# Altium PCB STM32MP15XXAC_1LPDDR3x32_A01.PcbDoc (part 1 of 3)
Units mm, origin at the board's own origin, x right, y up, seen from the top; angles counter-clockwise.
Board outline 89 x 120 mm, 6 copper layers (Top Layer, Signal Layer 1, Signal Layer 2, Signal Layer 3, Signal Layer 4, Bottom Layer), stack 1.556 mm thick; 93 components, 99 nets, 917 pads, 464 vias.
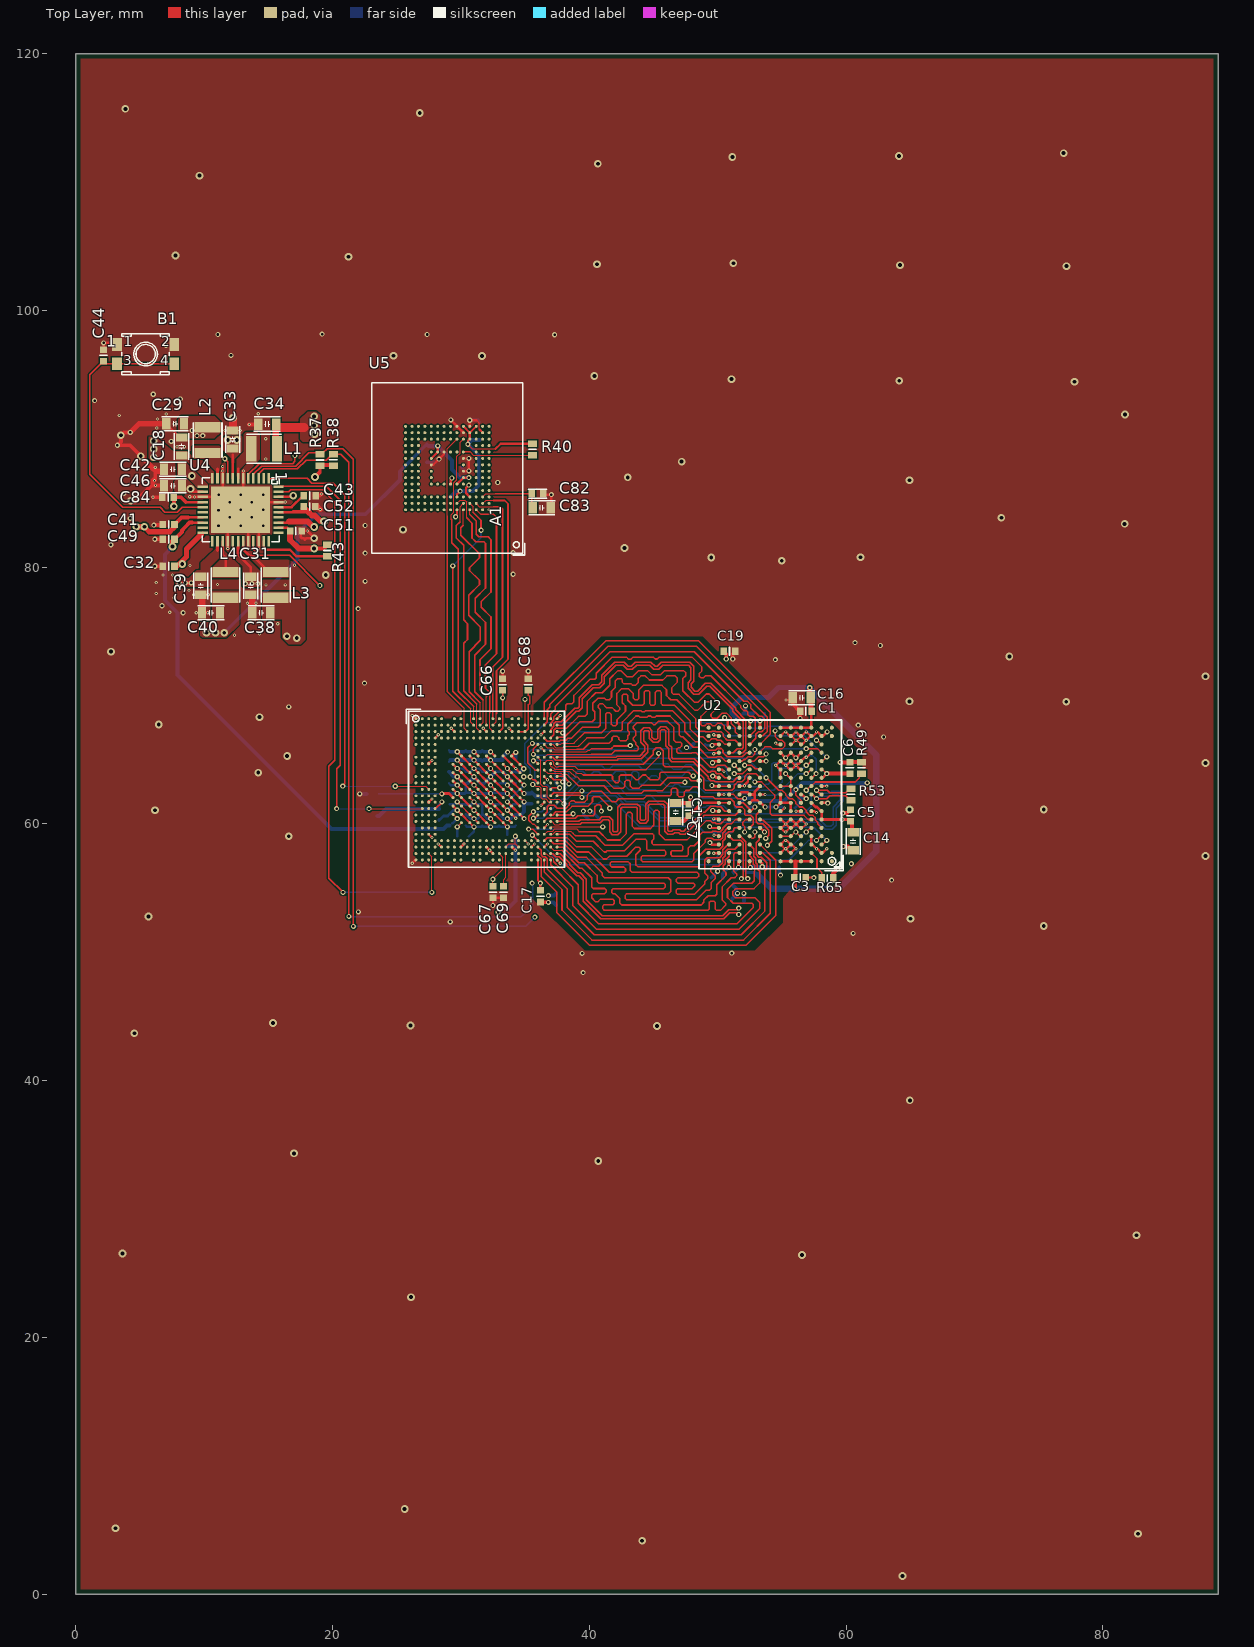
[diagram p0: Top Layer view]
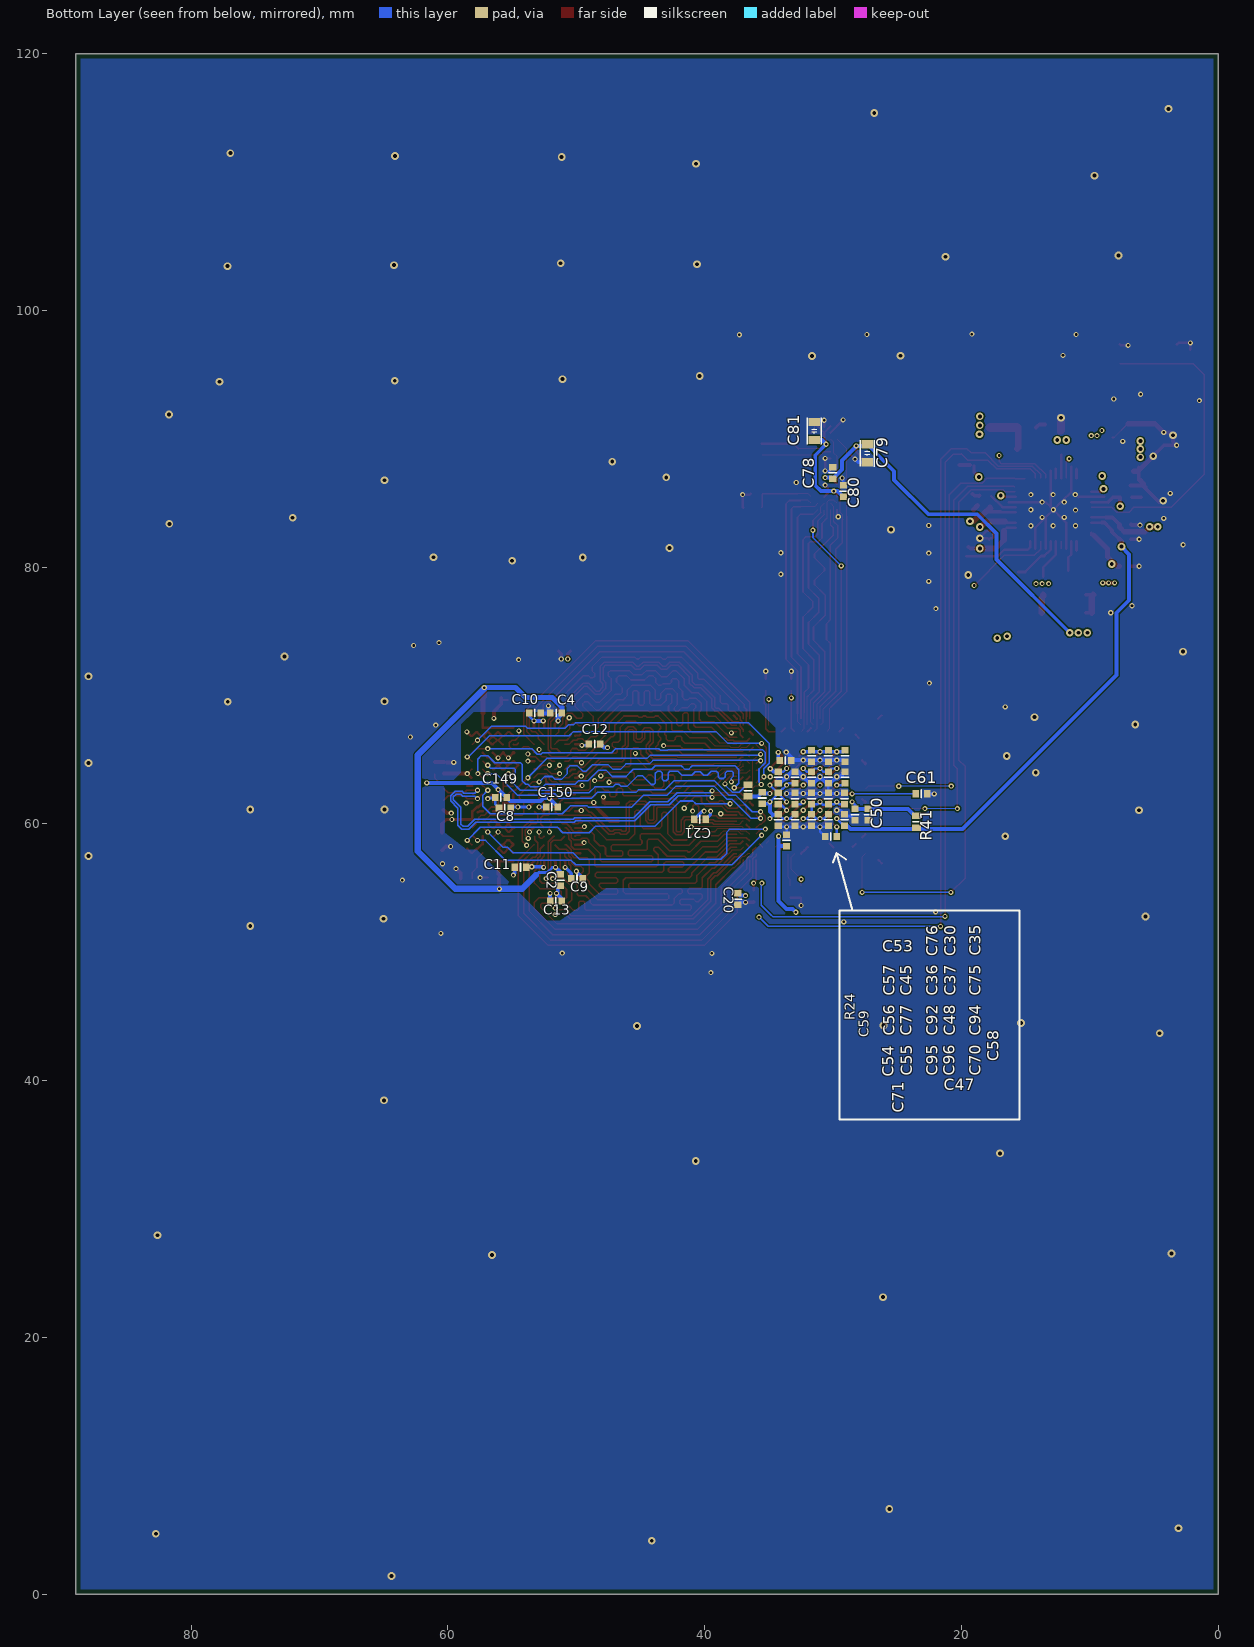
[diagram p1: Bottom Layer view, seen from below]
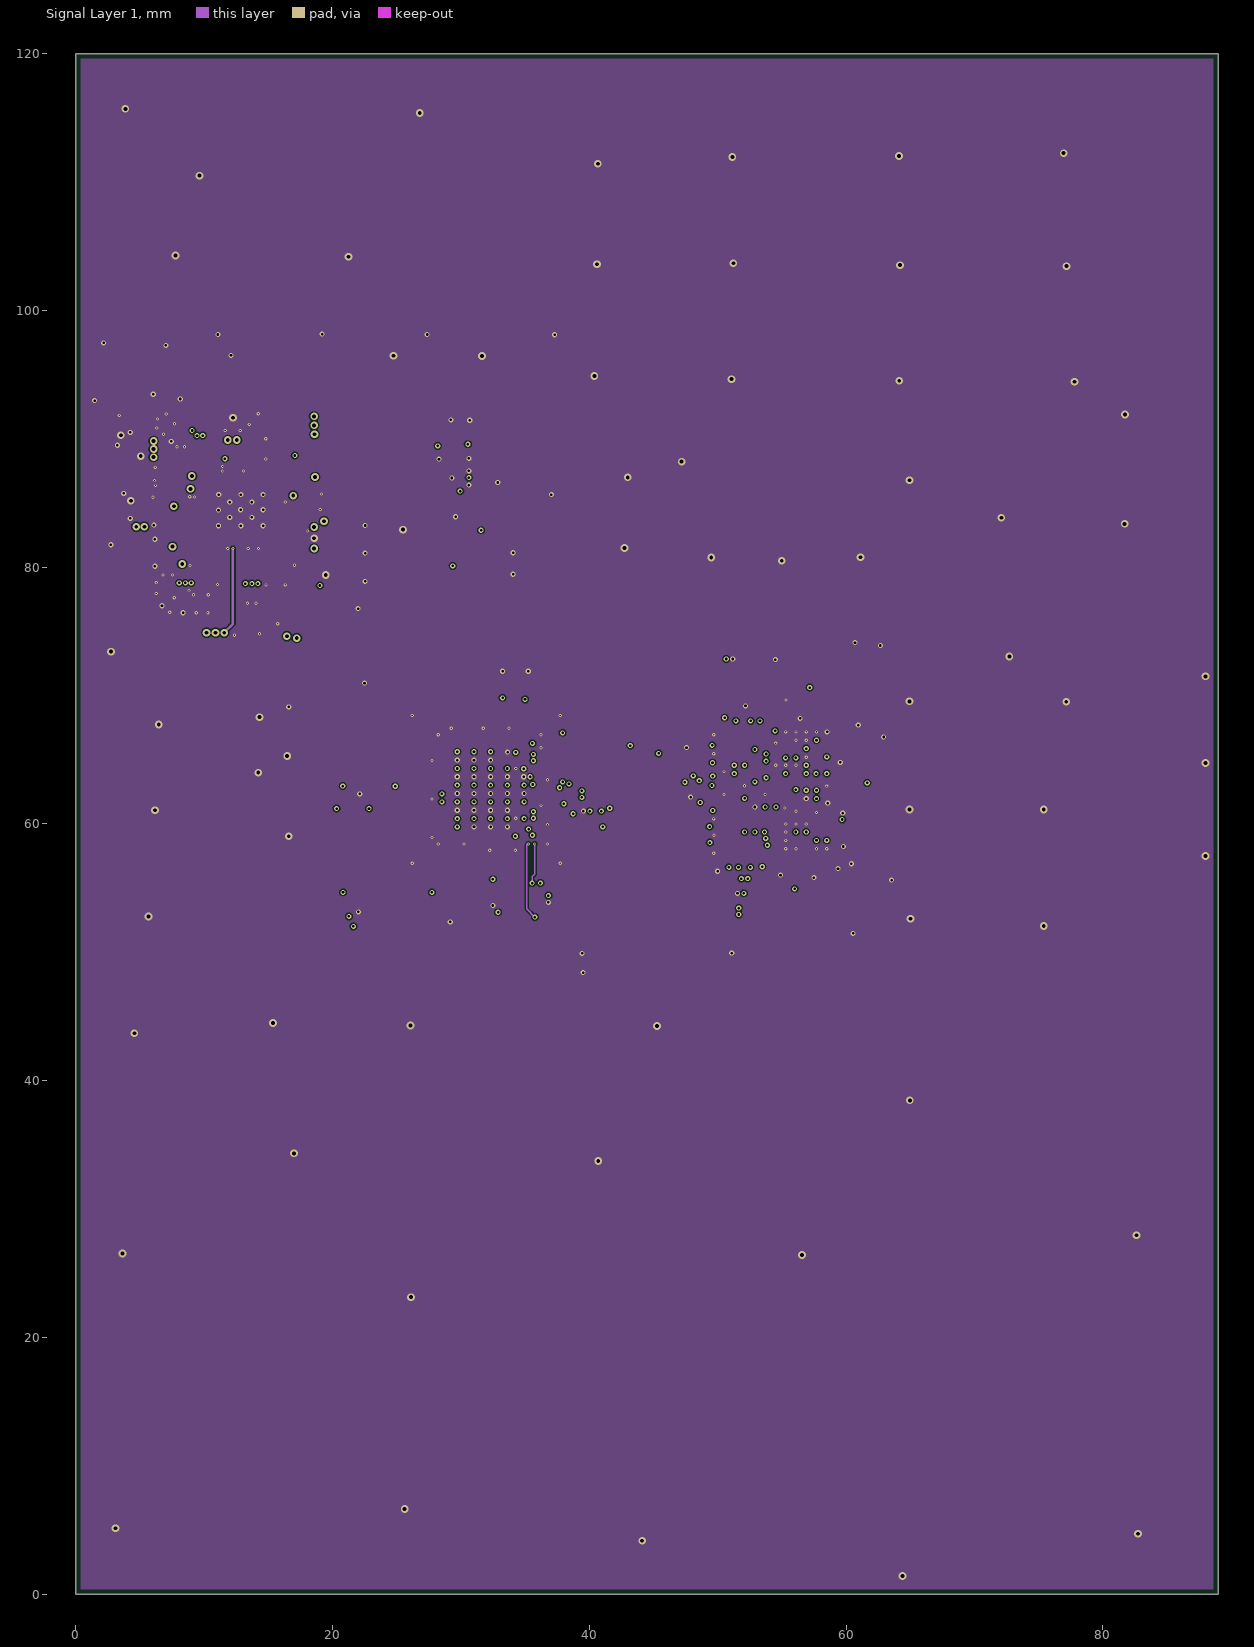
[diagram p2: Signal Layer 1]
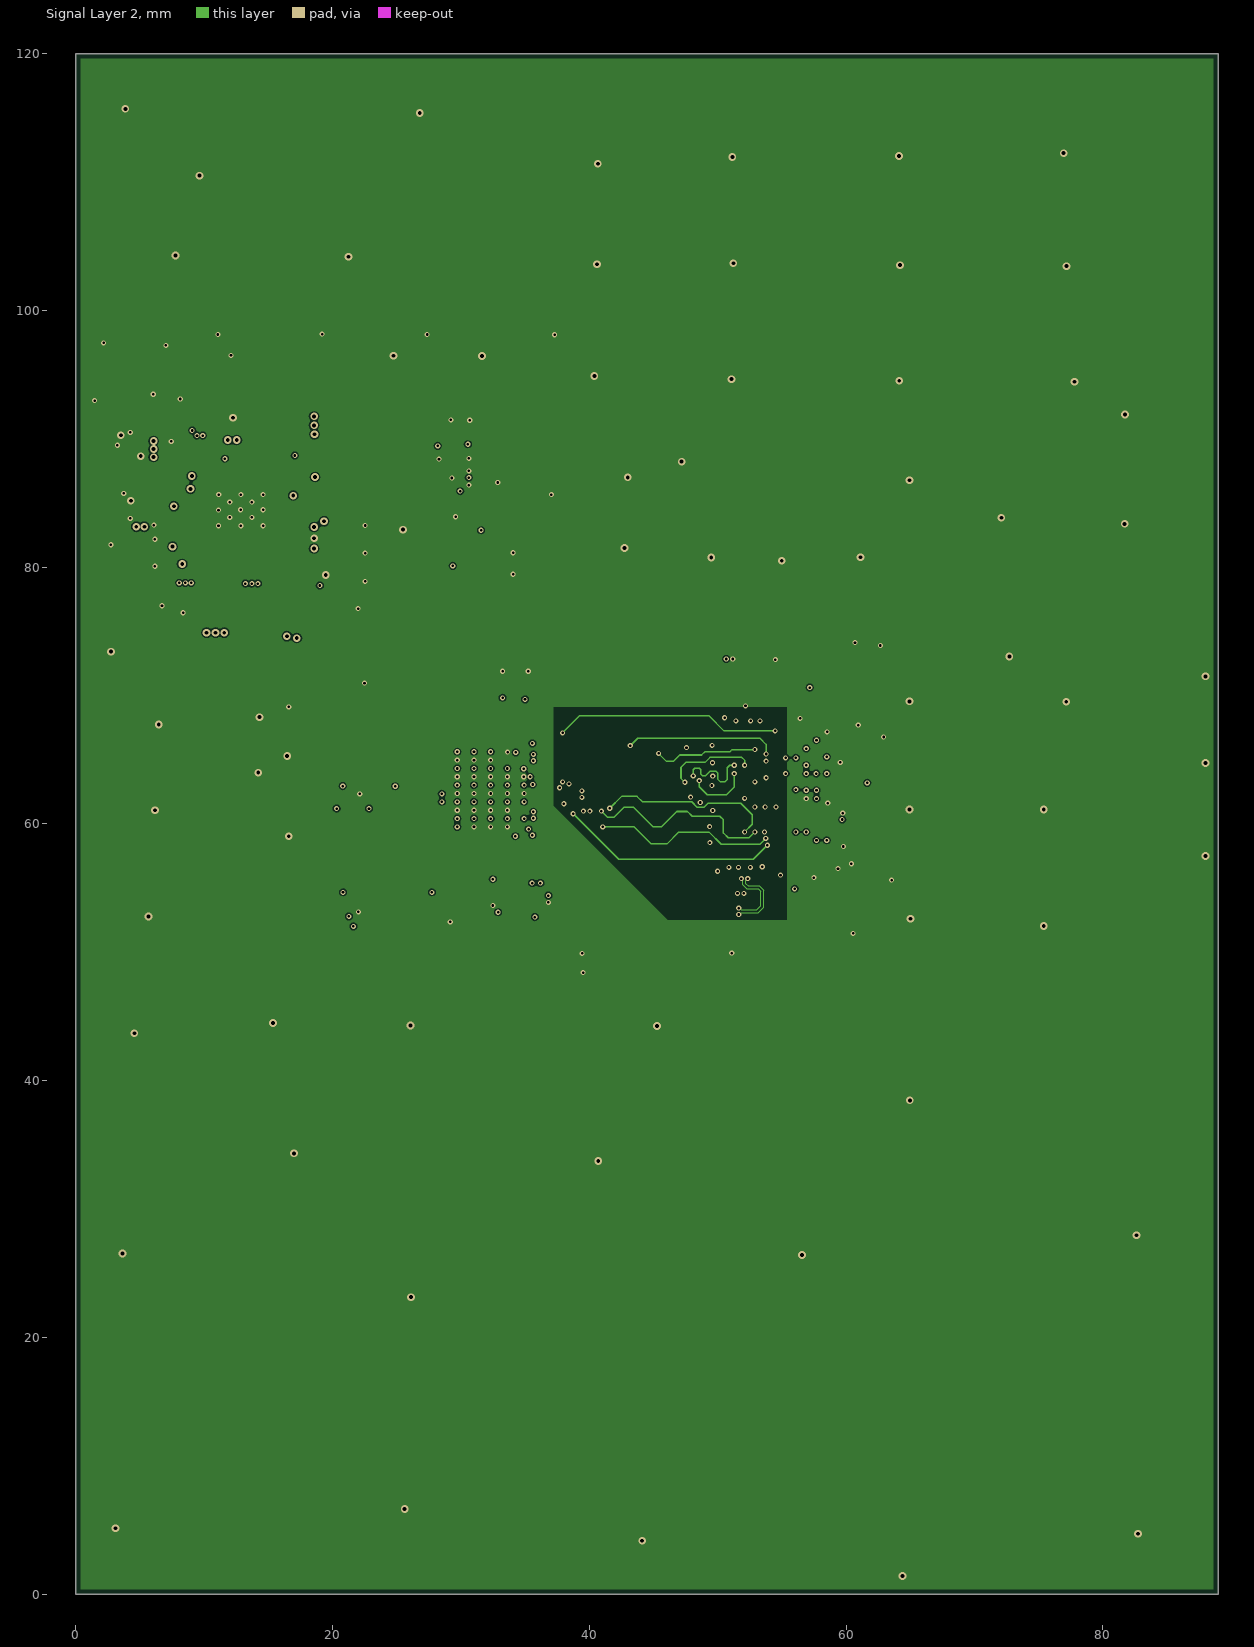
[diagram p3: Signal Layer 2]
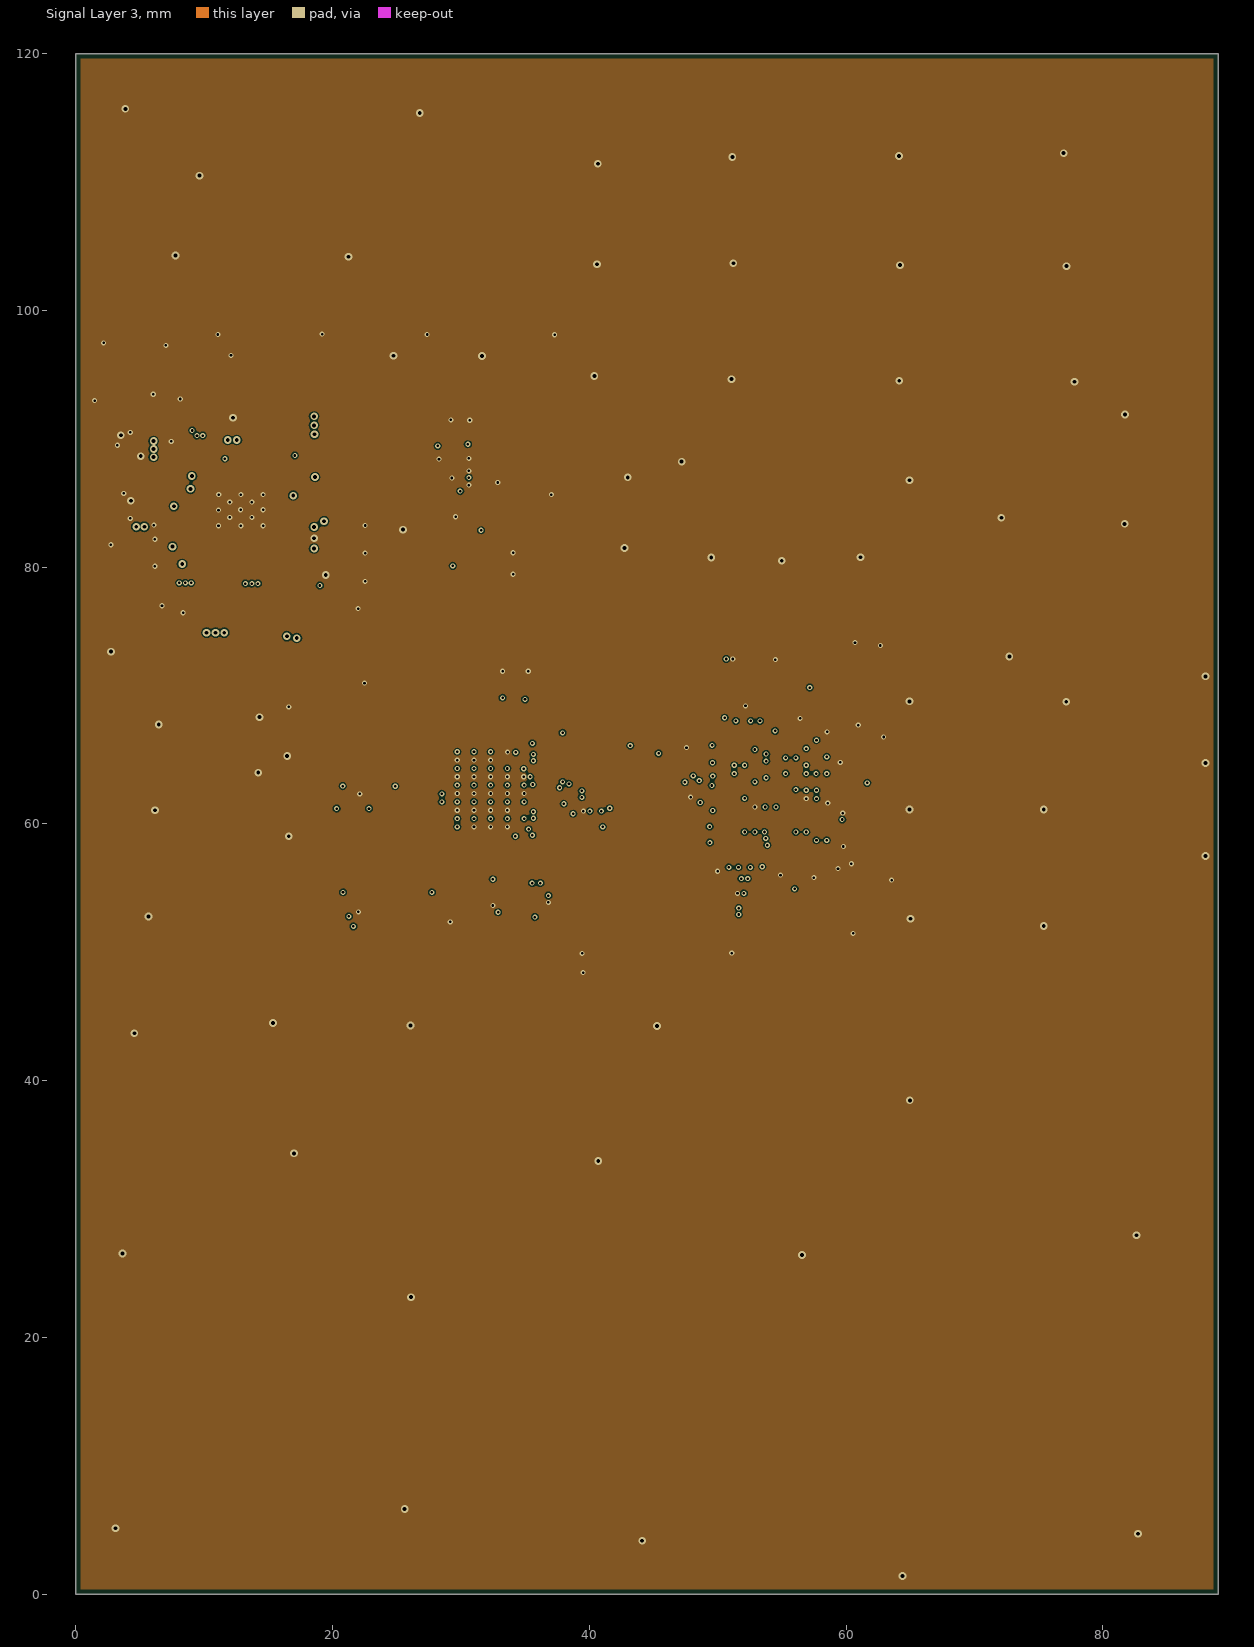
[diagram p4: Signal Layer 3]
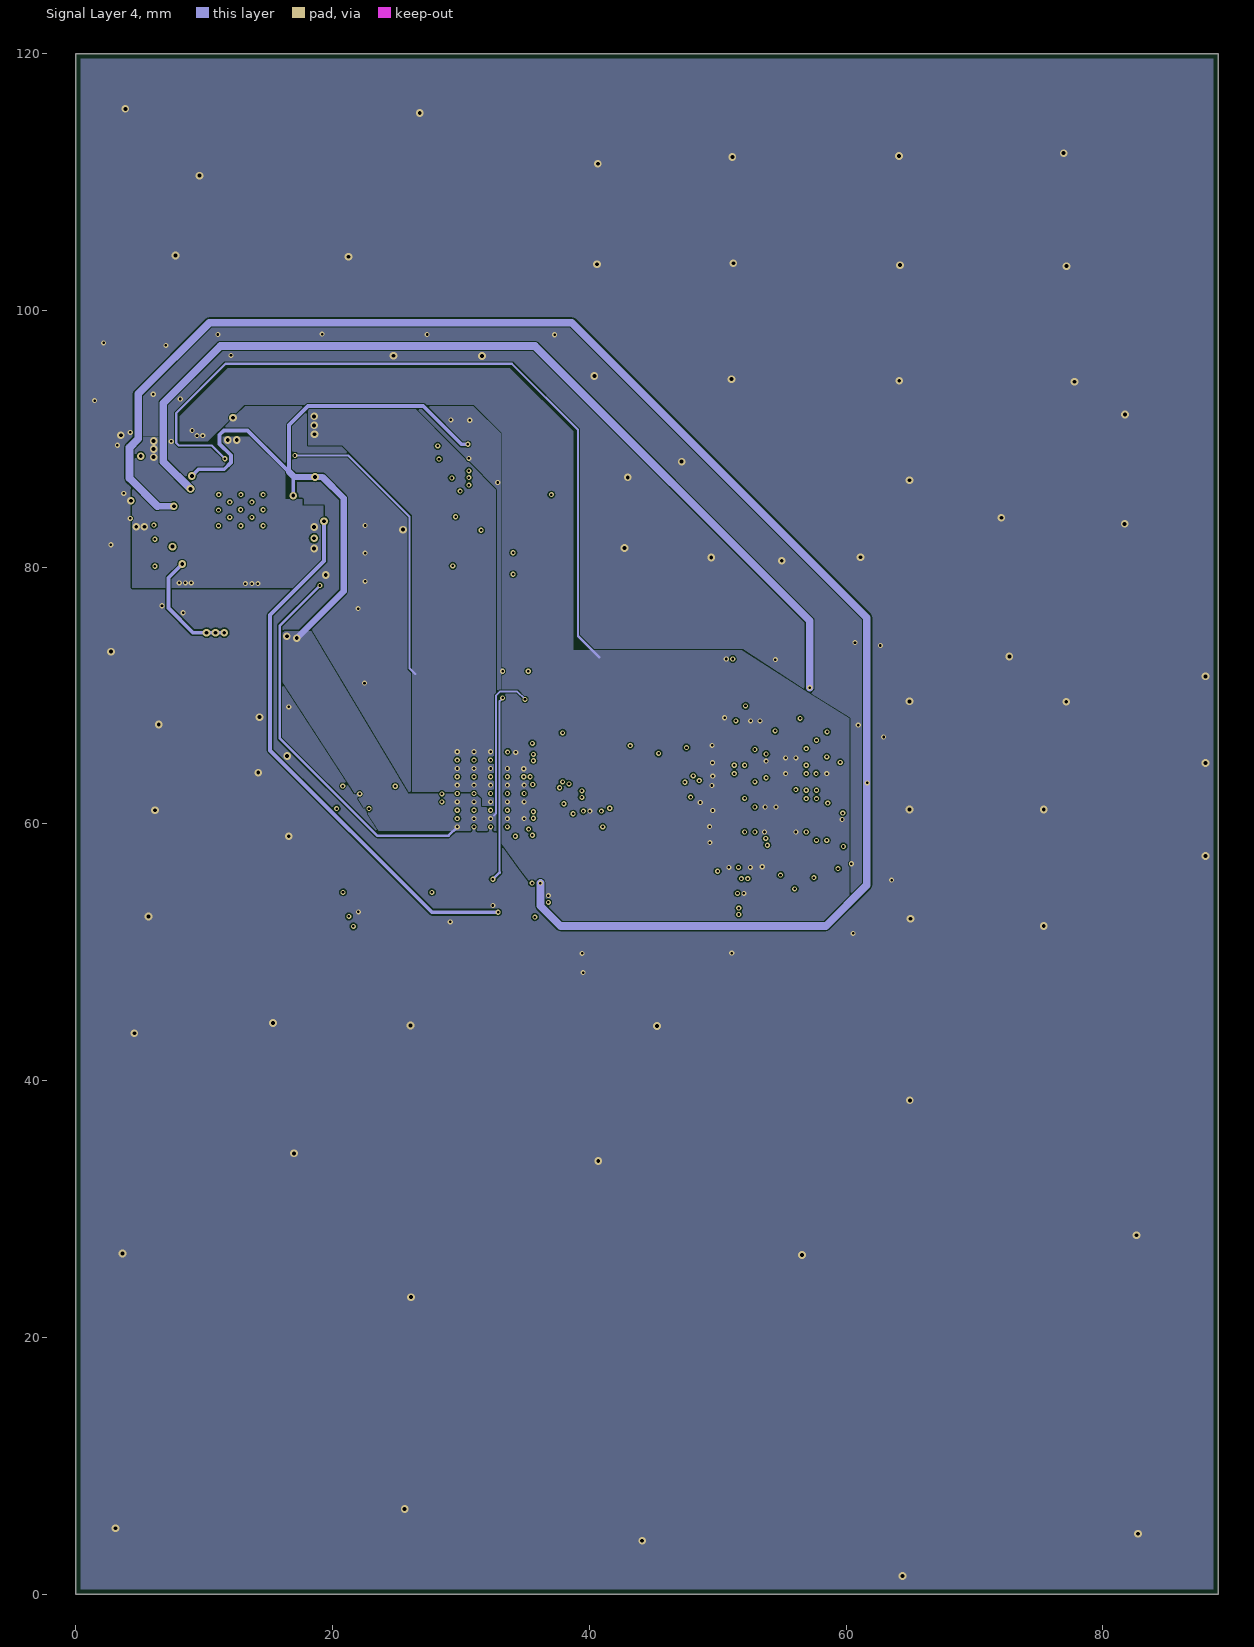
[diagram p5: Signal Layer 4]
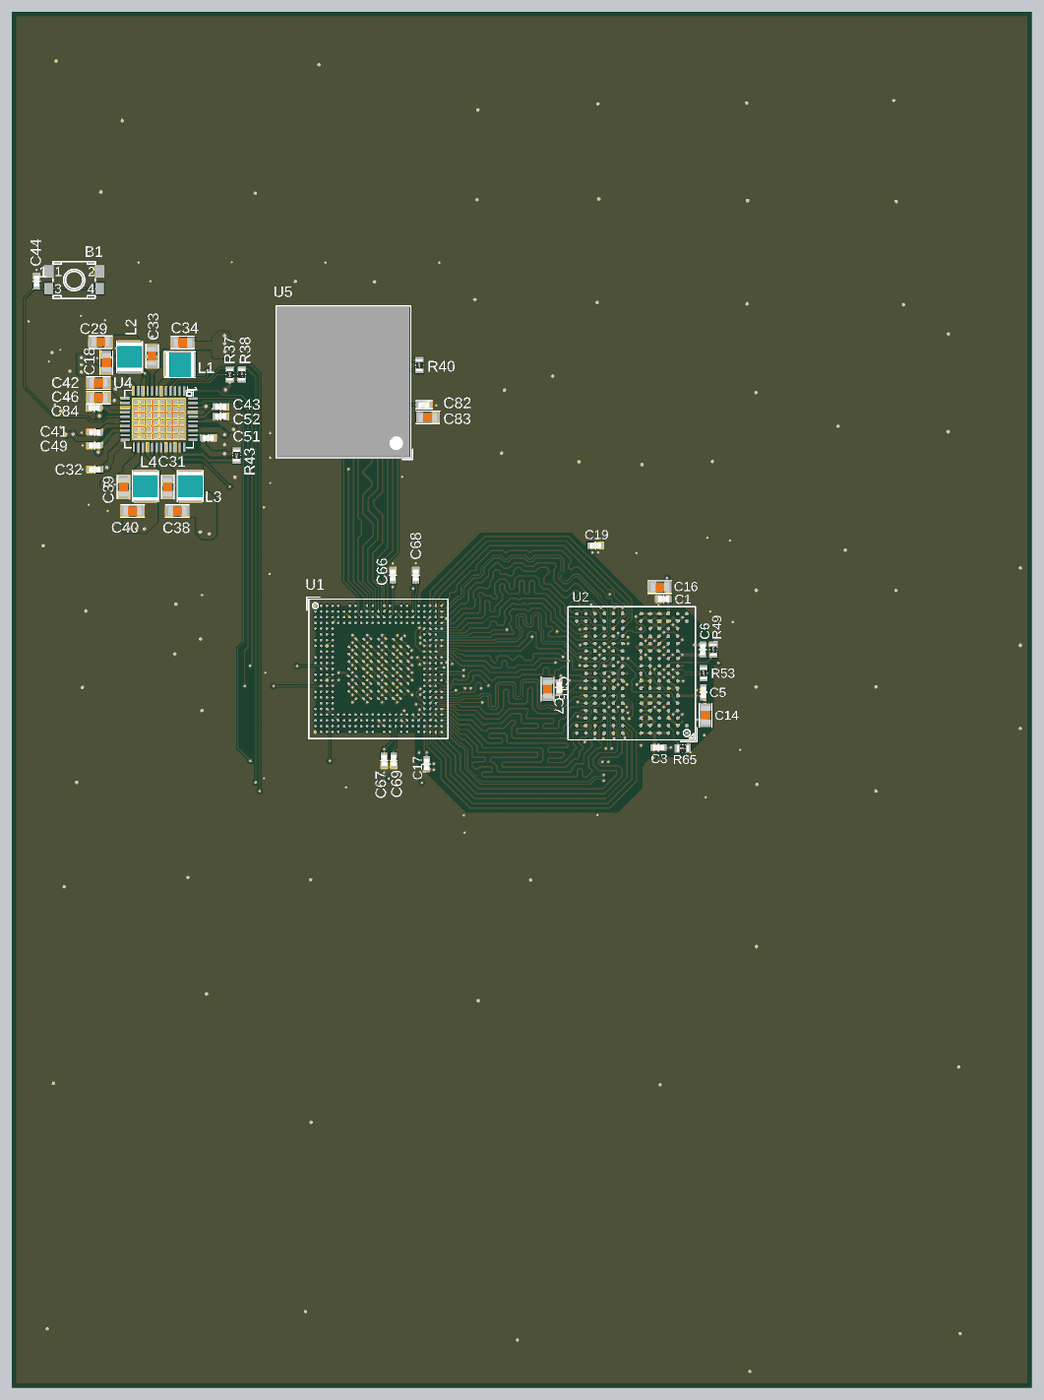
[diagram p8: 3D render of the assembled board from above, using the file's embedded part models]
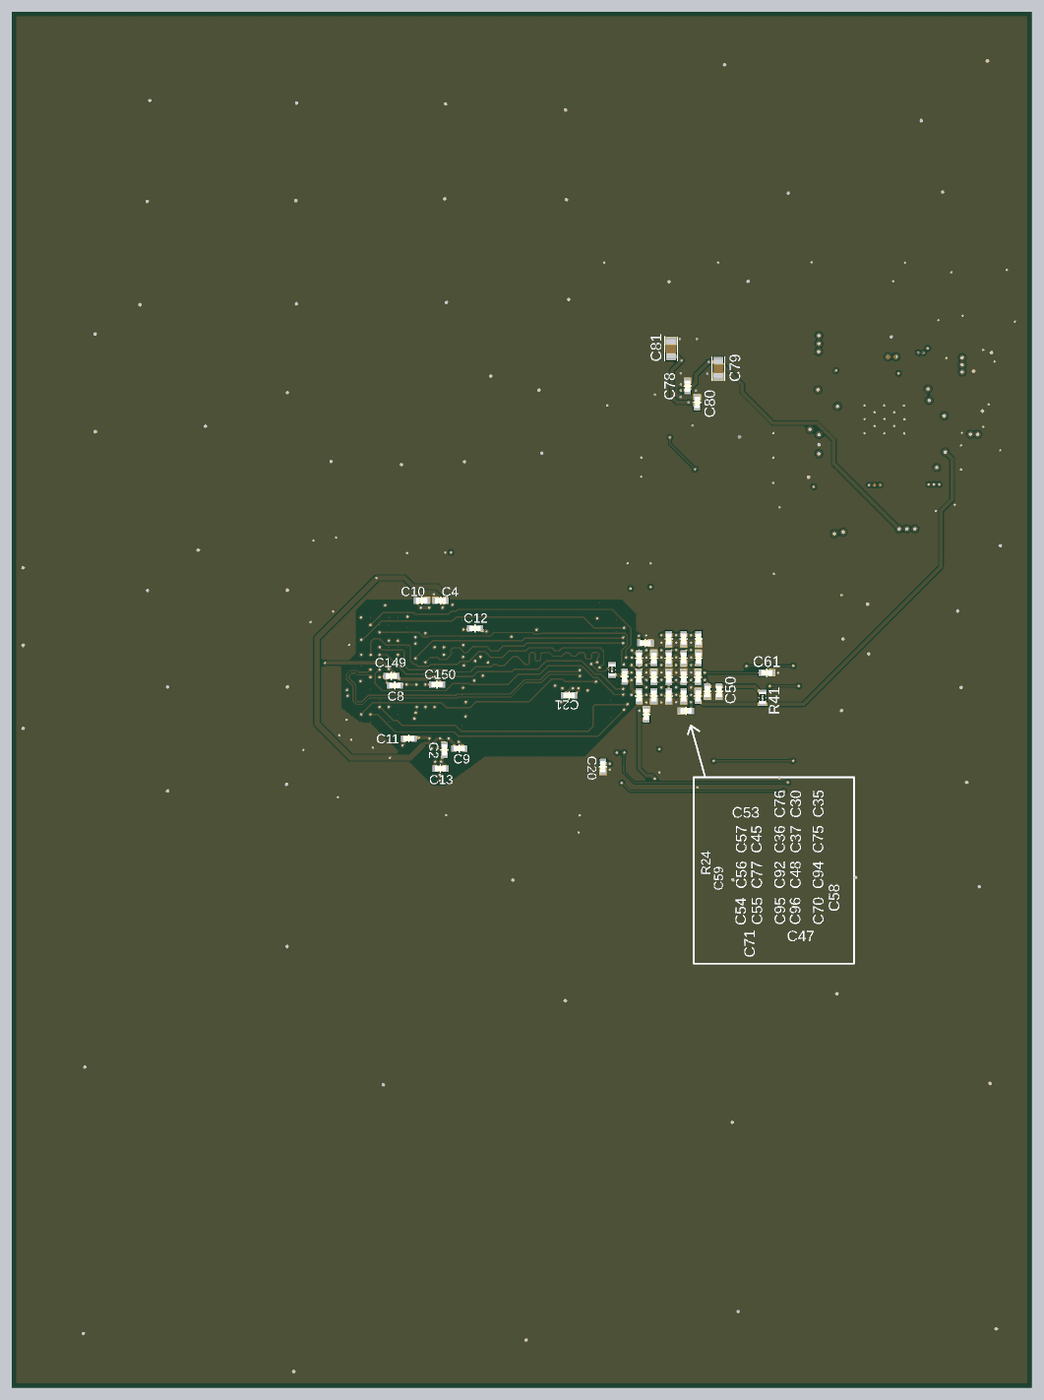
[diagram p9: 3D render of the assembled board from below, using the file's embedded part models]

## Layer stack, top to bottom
Top Solder: solder mask 0.0203, Solder Resist, Dk 3.5
Top Layer: signal copper 0.037
Dielectric 1: core 0.0986, FR-4, Dk 4.1
Signal Layer 1: signal copper 0.035
Dielectric 2: prepreg 0.13, Dk 4.25
Signal Layer 2: signal copper 0.035
Dielectric 3: core 0.885, Dk 4.25
Signal Layer 3: signal copper 0.035
Dielectric 4: prepreg 0.13, Dk 4.25
Signal Layer 4: signal copper 0.035
Dielectric 5: core 0.0986, Dk 4.1
Bottom Layer: signal copper 0.037
Bottom Solder: solder mask 0.0203, Solder Resist, Dk 3.5

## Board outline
89,120 89,0 0,0 0,120

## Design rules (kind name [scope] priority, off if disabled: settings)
BoardOutlineClearance [All] p1: gap=0.4 ignorepadtopadclearanceinfootprint=FALSE
Clearance diff [InNetClass('diff')] p1: gap=0.1 ignorepadtopadclearanceinfootprint=FALSE except(0: Arc-Hole Track-Hole SMDPad-Hole THPad-Hole Via-Hole Fill-Hole Poly-Hole Region-Hole Text-Hole; 0.08: Track-SMDPad; 0.15: Arc-Fill Track-Fill SMDPad-Fill THPad-Fill Via-Fill Fill-Fill; 0.2: Arc-THPad SMDPad-SMDPad SMDPad-THPad THPad-THPad; 0.3: Track-Track)
Clearance [InNetClass('All Nets')] p2: gap=0.1 ignorepadtopadclearanceinfootprint=FALSE except(0: Arc-Hole Track-Hole SMDPad-Hole THPad-Hole Via-Hole Fill-Hole Poly-Hole Region-Hole Text-Hole; 0.08: Track-Track Track-SMDPad; 0.15: Arc-Fill Track-Fill SMDPad-Fill THPad-Fill Via-Fill Fill-Fill)
ComponentClearance [All] p1 off: gap=0.025 collisioncheckmode=3 verticalgap=2540 showdistances=TRUE
DiffPairsRouting [All] p1: maxlimit=0.14 minlimit=0.13 mostfreqgap=0.14 toplayer_maxgap=0.13 toplayer_prefgap=0.13 toplayer_minwidth=0.09 toplayer_maxwidth=0.13 toplayer_prefwidth=0.1 midlayer1_maxgap=0.13 midlayer1_prefgap=0.13 midlayer1_minwidth=0.09 midlayer1_maxwidth=0.13 midlayer1_prefwidth=0.09 midlayer2_mingap=0.14 midlayer2_minwidth=0.09 midlayer2_maxwidth=0.09 midlayer2_prefwidth=0.09 midlayer3_mingap=0.14 midlayer3_minwidth=0.09 midlayer3_maxwidth=0.13 midlayer3_prefwidth=0.09 midlayer4_maxgap=0.13 midlayer4_prefgap=0.13 midlayer4_minwidth=0.09 midlayer4_maxwidth=0.13 midlayer4_prefwidth=0.09 bottomlayer_maxgap=0.13 bottomlayer_prefgap=0.13 bottomlayer_minwidth=0.09 bottomlayer_maxwidth=0.13 bottomlayer_prefwidth=0.1 maxuncoupledlength=0.5
FanoutControl Fanout_BGA [IsBGA] p1: bgadir=Out bgaviamode=Closest fanoutstyle=Auto fanoutdirection=Alternating viagrid=0.025 // Fanout_BGA (Default Rule)
FanoutControl Fanout_LCC [IsLCC] p2: bgadir=Out bgaviamode=Closest fanoutstyle=Auto fanoutdirection=Alternating viagrid=0.025 // Fanout_LCC (Default Rule)
FanoutControl Fanout_SOIC [IsSOIC] p3: bgadir=Out bgaviamode=Closest fanoutstyle=Auto fanoutdirection=Alternating viagrid=0.025 // Fanout_SOIC (Default Rule)
FanoutControl Fanout_Small [(CompPinCount < 5)] p4: bgadir=Out bgaviamode=Closest fanoutstyle=Auto fanoutdirection=OutThenIn viagrid=0.025 // Fanout_Small (Default Rule)
FanoutControl Fanout_Default [All] p5: bgadir=Out bgaviamode=Closest fanoutstyle=Auto fanoutdirection=Alternating viagrid=0.025 // Fanout_Default (Default Rule)
Height [All] p1 off: minheight=0 maxheight=100 prefheight=0.5
HoleSize [All] p1: absolutevalues=TRUE maxlimit=10 minlimit=0.1 maxpercent=80.000 minpercent=20.000
HoleToHoleClearance [All] p1: gap=0.25 allowstackedmicrovias=TRUE
Length Length_SDMMC1 [InNetClass('NETC_SDMMC1')] p1: maxlimit=86 minlimit=81
MatchedLengths [All] p1: tolerance=25.4 checknetsindiffpair=FALSE checkdiffpairvsdiffpair=TRUE checkxsignals=TRUE checkothers=TRUE
MinimumSolderMaskSliver [All] p1: minsoldermaskwidth=0
PlaneClearance [All] p1: clearance=0.6
PlaneConnect [All] p1: planeconnectstyle=Direct reliefexpansion=0.508 reliefentries=4 reliefconductorwidth=0.254 reliefairgap=0.254
PolygonConnect PolygonConnect_notr [All vs (IsNamedPolygon('NO TR'))] p1: connectstyle=Direct reliefconductorwidth=0.254 reliefentries=4 polygonreliefangle="90 Angle" airgapwidth=0.254
PolygonConnect PolygonConnect_VTT_DDR [All vs IsNamedPolygon('VTT_DDR_BOT')] p2: connectstyle=Direct reliefconductorwidth=0.254 reliefentries=4 polygonreliefangle="45 Angle" airgapwidth=0.254
PolygonConnect [All] p3: connectstyle=Direct reliefconductorwidth=0.254 reliefentries=4 polygonreliefangle="45 Angle" airgapwidth=0.254
RoomDefinition U_1LPDDR3_32bits [InComponentClass('U_1LPDDR3_32bits')] p1 off: confinementstyle=ConfineIn formatcopy=TRUE lockcomponents=FALSE outline 90.122,1.416 267.981,1.416 267.981,16.341 90.122,16.341
RoomDefinition U_STM32_MPU_IOs [InComponentClass('U_STM32_MPU_IOs')] p2 off: confinementstyle=ConfineIn formatcopy=TRUE lockcomponents=FALSE outline 88.575,2.075 139.375,2.075 139.375,27.475 88.575,27.475
RoomDefinition U_Power_MPU [InComponentClass('U_Power_MPU')] p3 off: confinementstyle=ConfineIn formatcopy=TRUE lockcomponents=FALSE outline 87.122,16.916 100.898,16.916 100.898,22.892 87.122,22.892
RoomDefinition U_eMMC [InComponentClass('U_eMMC')] p4 off: confinementstyle=ConfineIn formatcopy=TRUE lockcomponents=FALSE outline 87.122,1.416 129.449,1.416 129.449,15.666 87.122,15.666
RoomDefinition U_Power_PMIC [InComponentClass('U_Power_PMIC')] p5 off: confinementstyle=ConfineIn formatcopy=TRUE lockcomponents=FALSE outline 87.122,8.666 203.578,8.666 203.578,17.666 87.122,17.666
RoutingVias RoutingVias_GND [InNetClass('GND')] p1: holewidth=0.3 width=0.6 viastyle="Through Hole" minholewidth=0.1 minwidth=0.25 maxholewidth=0.3 maxwidth=0.6
RoutingVias RoutingVias_ALIMS [InNetClass('ALIMS')] p2: holewidth=0.3 width=0.6 viastyle="Through Hole" minholewidth=0.2 minwidth=0.4 maxholewidth=0.3 maxwidth=0.6
RoutingVias [All] p3: holewidth=0.2 width=0.4 viastyle="Through Hole" minholewidth=0.1 minwidth=0.25 maxholewidth=0.3 maxwidth=0.6
SilkToSilkClearance [All] p1: silktosilkclearance=0
SilkToSolderMaskClearance [IsPad] p1: minsilkscreentomaskgap=0 clearancetoexposedcopper=TRUE
SolderMaskExpansion [All] p1: expansion=0.05 istentingtop=FALSE
Width VDD2_DDR [InNet('VDD2_DDR')] p1: maxlimit=0.5 minlimit=0.1 preferedwidth=0.3
Width Width_VCORE [InNet('VDD_CORE')] p2: maxlimit=0.7 minlimit=0.1 preferedwidth=0.3 midlayer1_minwidth=0.12 midlayer2_minwidth=0.12 midlayer3_minwidth=0.12 midlayer4_minwidth=0.12 bottomlayer_minwidth=0.12 minimp=50.000000 maximp=50.000000 favimp=50.000000
Width Width_gnd [InNet('GND')] p3: maxlimit=0.7 minlimit=0.09 preferedwidth=0.3
Width [All] p4: maxlimit=0.6 minlimit=0.09 preferedwidth=0.127 toplayer_prefwidth=0.12 midlayer1_minwidth=0.1 midlayer1_prefwidth=0.12 midlayer2_prefwidth=0.12 midlayer3_minwidth=0.127 midlayer4_minwidth=0.1 midlayer4_prefwidth=0.12 bottomlayer_prefwidth=0.12 minimp=50.000000 maximp=50.000000 favimp=50.000000
15 further rules are at their usual default settings.

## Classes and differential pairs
component class U_1LPDDR3_32bits: C1 C2 C3 C4 C5 C6 C7 C8 C9 C10 C11 C12 C13 C14 C15 C16 C19 C20 C21 C149 C150 R49 R53 R65 U2
differential pair class DIFF_CLK: DDR_CLK
differential pair class DIFF_DQS1: DDR_DQS1
differential pair class DIFF_DQS0: DDR_DQS0
polygon class POLY_DIRECT_ALL: NETC906_2_L01_P192
component class U_Power_MPU: C30 C35 C36 C37 C45 C47 C48 C50 C53 C54 C55 C56 C57 C58 C59 C61 C66 C67 C68 C69 C70 C71 C75 C76 C77 C92 C94 C95 C96 R41
component class U_Power_PMIC: B1 C18 C29 C31 C32 C33 C34 C38 C39 C40 C41 C42 C43 C44 C46 C49 C51 C52 C84 L1 L2 L3 L4 R43 U4
component class U_eMMC: C78 C79 C80 C81 C82 C83 R40 U5
component class U_STM32_MPU_IOs: C17 R24 R37 R38 U1
net class eMMC_SDIO2_D[0..7]: eMMC_SDIO2_D0 eMMC_SDIO2_D1 eMMC_SDIO2_D2 eMMC_SDIO2_D3 eMMC_SDIO2_D4 eMMC_SDIO2_D5 eMMC_SDIO2_D6 eMMC_SDIO2_D7
differential pair DDR_CLK: +DDR_CLK_P -DDR_CLK_N
differential pair DDR_DQS0: +DDR_DQS0_P -DDR_DQS0_N
differential pair DDR_DQS1: +DDR_DQS1_P -DDR_DQS1_N
differential pair DDR_DQS2: +DDR_DQS2_P -DDR_DQS2_N
differential pair DDR_DQS3: +DDR_DQS3_P -DDR_DQS3_N

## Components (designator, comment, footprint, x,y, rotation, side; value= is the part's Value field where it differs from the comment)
B1 "SW-PUSH-TS-02H-Blue" SWI_JIUBABA_C-TS-02H-2-5-B-V-T_R_BLUE 5.45,96.6 r0 top
C1 "Capacitor" C0402 56.875,68.775 r180 top
C2 "Capacitor" C0402 51.25,55.625 r270 bottom
C3 "Capacitor" C0402 56.425,55.825 r0 top
C4 "Capacitor" C0402 51.575,68.65 r0 bottom
C5 "Capacitor" C0402 60.35,60.65 r90 top
C6 "Capacitor" C0402 60.3,64.375 r90 top
C7 "Capacitor" C0402 47.775,61.075 r90 top
C8 "Capacitor" C0402 55.575,61.25 r0 bottom
C9 "Capacitor" C0402 49.95,55.75 r180 bottom
C10 "Capacitor" C0402 53.225,68.65 r180 bottom
C11 "Capacitor" C0402 54.35,56.625 r0 bottom
C12 "Capacitor" C0402 48.575,66.225 r180 bottom
C13 "Capacitor" C0402 51.6,54 r180 bottom
C14 "Capacitor" C0603 60.55,58.65 r90 top
C15 "Capacitor" C0603 46.75,60.925 r270 top
C16 "Capacitor" C0603 56.55,69.825 r0 top
C17 "Capacitor" C0402 36.2,54.375 r270 top
C18 "Capacitor" C0603 8.25,89.4 r270 top
C19 "Capacitor" C0402 50.925,73.45 r0 top
C20 "Capacitor" C0402 37.425,54.15 r270 bottom
C21 "Capacitor" C0402 40.375,60.375 r180 bottom
C29 "Capacitor" C0603 7.75,91.175 r0 top
C30 "Capacitor" C0402 30.375,65.3 r90 bottom
C31 "Capacitor" C0603 13.625,78.55 r90 top
C32 "Capacitor" C0402 7.25,80.075 r0 top
C33 "Capacitor" C0603 12.25,89.95 r270 top
C34 "Capacitor" C0603 14.925,91.15 r0 top
C35 "Capacitor" C0402 29.075,65.3 r90 bottom
C36 "Capacitor" C0402 31.675,63.625 r90 bottom
C37 "Capacitor" C0402 30.375,63.625 r90 bottom
C38 "Capacitor" C0603 14.45,76.45 r0 top
C39 "Capacitor" C0603 9.75,78.55 r90 top
C40 "Capacitor" C0603 10.55,76.45 r0 top
C41 "Capacitor" C0402 7.25,83.325 r0 top
C42 "Capacitor" C0603 7.575,87.625 r0 top
C43 "Capacitor" C0402 18.234,85.562 r0 top
C44 "Capacitor" C0402 2.175,96.5 r270 top
C45 "Capacitor" C0402 32.975,63.625 r270 bottom
C46 "Capacitor" C0603 7.575,86.35 r0 top
C47 "Capacitor" C0402 30.175,59.025 r180 bottom
C48 "Capacitor" C0402 30.375,61.975 r270 bottom
C49 "Capacitor" C0402 7.25,82.175 r0 top
C50 "Capacitor" C0402 27.275,60.725 r90 bottom
C51 "Capacitor" C0402 17.15,82.825 r180 top
C52 "Capacitor" C0402 18.225,84.725 r180 top
C53 "Capacitor" C0402 33.725,64.95 r0 bottom
C54 "Capacitor" C0402 34.275,60.325 r90 bottom
C55 "Capacitor" C0402 32.975,60.325 r90 bottom
C56 "Capacitor" C0402 34.275,61.975 r90 bottom
C57 "Capacitor" C0402 34.275,63.625 r90 bottom
C58 "Capacitor" C0402 28.3,60.725 r90 bottom
C59 "Capacitor" C0402 35.525,62.025 r270 bottom
C61 "Capacitor" C0402 23.125,62.35 r0 bottom
C66 "Capacitor" C0402 33.25,70.85 r270 top
C67 "Capacitor" C0402 32.5,54.7 r90 top
C68 "Capacitor" C0402 35.25,70.85 r270 top
C69 "Capacitor" C0402 33.325,54.7 r90 top
C70 "Capacitor" C0402 29.125,60.325 r270 bottom
C71 "Capacitor" C0402 33.625,58.725 r270 bottom
C75 "Capacitor" C0402 29.075,63.625 r270 bottom
C76 "Capacitor" C0402 31.675,65.3 r90 bottom
C77 "Capacitor" C0402 32.975,61.975 r270 bottom
C78 "Capacitor" C0402 30.025,87.35 r270 bottom
C79 "Capacitor" C0603 27.35,88.875 r90 bottom
C80 "Capacitor" C0402 29.2,85.925 r270 bottom
C81 "Capacitor" C0603 31.475,90.6 r270 bottom
C82 "Capacitor" C0402 35.975,85.725 r180 top
C83 "Capacitor" C0603 36.3,84.625 r180 top
C84 "Capacitor" C0402 7.2,85.45 r0 top
C92 "Capacitor" C0402 31.675,61.975 r270 bottom
C94 "Capacitor" C0402 29.125,61.975 r270 bottom
C95 "Capacitor" C0402 31.675,60.325 r90 bottom
C96 "Capacitor" C0402 30.375,60.325 r90 bottom
C149 "Capacitor" C0402 55.875,62.075 r0 bottom
C150 "Capacitor" C0402 51.9,61.325 r0 bottom
L1 "IND_1uH_42mohm_3.2A" IND_2520_TOKO_DFE252012P 14.675,89.225 r0 top
L2 "IND_1uH_42mohm_3.2A" IND_2520_TOKO_DFE252012P 10.275,89.9 r90 top
L3 "IND_1uH_42mohm_3.2A" IND_2520_TOKO_DFE252012P 15.575,78.625 r270 top
L4 "IND_1uH_42mohm_3.2A" IND_2520_TOKO_DFE252012P 11.675,78.625 r270 top
R24 "Resistor" R0402 36.625,62.6 r270 bottom
R37 "Resistor" R0402 19.025,88.35 r90 top
R38 "Resistor" R0402 20.074,88.363 r90 top
R40 "Resistor" R0402 35.575,89.175 r90 top
R41 "Resistor" R0402 23.5,60.175 r90 bottom
R43 "Resistor" R0402 19.625,81.3 r90 top
R49 "Resistor" R0402 61.2,64.37 r270 top
R53 "Resistor" R0402 60.375,62.31 r90 top
R65 "Resistor" R0402 58.55,55.75 r0 top
U1 "STM32MP157CAC3" ICC_TFBGA361_12X12_STM32MP157CAC3_P050-065 32,62.7 r0 top locked
U2 "H9CCNNN8GTALAR-NUD" ICC_FBGA178_11X11P5_P080-065 54.1,62.3 r180 top locked
U4 "STPMU1" ICC_WFQFN44-EPAD_5X6_P040 12.85,84.475 r270 top
U5 "eMMC_THGBMDG5D1LBAIL" ICC_P-WFBGA153_13X11P5_P050 28.95,87.725 r90 top locked

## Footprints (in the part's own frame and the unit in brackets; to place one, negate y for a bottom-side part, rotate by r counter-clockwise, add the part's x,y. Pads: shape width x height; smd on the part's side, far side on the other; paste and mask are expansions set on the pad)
C0402 [mm]
  rect 0.51x0.56 smd mask+0.05: 1(-0.45,0) 2(0.45,0)
  silkscreen extent 0,-0.3 0,0.3, body extent -0.5,-0.3 0.5,0.3, height 0.4
C0603 [mm]
  rect 0.64x0.89 smd mask+0.05: 1(-0.7,0) 2(0.7,0)
  silkscreen extent -1.05,-0.55 1.02,0.55, body extent -0.9,-0.5 0.9,0.5, height 1.4
ICC_FBGA178_11X11P5_P080-065 [mm]
  round 0.32 smd mask+0.05: A1(-4.8,5.2) A2(-4,5.2) A3(-3.2,5.2) A4(-2.4,5.2) A5(-1.6,5.2) A6(-0.8,5.2) A8(0.8,5.2) A9(1.6,5.2) A10(2.4,5.2) A11(3.2,5.2) A12(4,5.2) A13(4.8,5.2) B1(-4.8,4.55) B2(-4,4.55) B3(-3.2,4.55) B4(-2.4,4.55) B5(-1.6,4.55) B6(-0.8,4.55) B8(0.8,4.55) B9(1.6,4.55) B10(2.4,4.55) B11(3.2,4.55) B12(4,4.55) B13(4.8,4.55) C2(-4,3.9) C3(-3.2,3.9) C4(-2.4,3.9) C5(-1.6,3.9) C6(-0.8,3.9) C8(0.8,3.9) C9(1.6,3.9) C10(2.4,3.9) C11(3.2,3.9) C12(4,3.9) D2(-4,3.25) D3(-3.2,3.25) D4(-2.4,3.25) D5(-1.6,3.25) D6(-0.8,3.25) D8(0.8,3.25) D9(1.6,3.25) D10(2.4,3.25) D11(3.2,3.25) D12(4,3.25) E2(-4,2.6) E3(-3.2,2.6) E4(-2.4,2.6) E5(-1.6,2.6) E6(-0.8,2.6) E8(0.8,2.6) E9(1.6,2.6) E10(2.4,2.6) E11(3.2,2.6) E12(4,2.6) F2(-4,1.95) F3(-3.2,1.95) F4(-2.4,1.95) F5(-1.6,1.95) F6(-0.8,1.95) F8(0.8,1.95) F9(1.6,1.95) F10(2.4,1.95) F11(3.2,1.95) F12(4,1.95) G2(-4,1.3) G3(-3.2,1.3) G4(-2.4,1.3) G5(-1.6,1.3) G6(-0.8,1.3) G8(0.8,1.3) G9(1.6,1.3) G10(2.4,1.3) G11(3.2,1.3) G12(4,1.3) H2(-4,0.65) H3(-3.2,0.65) H4(-2.4,0.65) H5(-1.6,0.65) H6(-0.8,0.65) H8(0.8,0.65) H9(1.6,0.65) H10(2.4,0.65) H11(3.2,0.65) H12(4,0.65) J2(-4,0) J3(-3.2,0) J4(-2.4,0) J5(-1.6,0) J6(-0.8,0) J8(0.8,0) J9(1.6,0) J10(2.4,0) J11(3.2,0) J12(4,0) K2(-4,-0.65) K3(-3.2,-0.65) K4(-2.4,-0.65) K5(-1.6,-0.65) K6(-0.8,-0.65) K8(0.8,-0.65) K9(1.6,-0.65) K10(2.4,-0.65) K11(3.2,-0.65) K12(4,-0.65) L2(-4,-1.3) L3(-3.2,-1.3) L4(-2.4,-1.3) L5(-1.6,-1.3) L6(-0.8,-1.3) L8(0.8,-1.3) L9(1.6,-1.3) L10(2.4,-1.3) L11(3.2,-1.3) L12(4,-1.3) M2(-4,-1.95) M3(-3.2,-1.95) M4(-2.4,-1.95) M5(-1.6,-1.95) M6(-0.8,-1.95) M8(0.8,-1.95) M9(1.6,-1.95) M10(2.4,-1.95) M11(3.2,-1.95) M12(4,-1.95) N2(-4,-2.6) N3(-3.2,-2.6) N4(-2.4,-2.6) N5(-1.6,-2.6) N6(-0.8,-2.6) N8(0.8,-2.6) N9(1.6,-2.6) N10(2.4,-2.6) N11(3.2,-2.6) N12(4,-2.6) P2(-4,-3.25) P3(-3.2,-3.25) P4(-2.4,-3.25) P5(-1.6,-3.25) P6(-0.8,-3.25) P8(0.8,-3.25) P9(1.6,-3.25) P10(2.4,-3.25) P11(3.2,-3.25) P12(4,-3.25) R2(-4,-3.9) R3(-3.2,-3.9) R4(-2.4,-3.9) R5(-1.6,-3.9) R6(-0.8,-3.9) R8(0.8,-3.9) R9(1.6,-3.9) R10(2.4,-3.9) R11(3.2,-3.9) R12(4,-3.9) T1(-4.8,-4.55) T2(-4,-4.55) T3(-3.2,-4.55) T4(-2.4,-4.55) T5(-1.6,-4.55) T6(-0.8,-4.55) T8(0.8,-4.55) T9(1.6,-4.55) T10(2.4,-4.55) T11(3.2,-4.55) T12(4,-4.55) T13(4.8,-4.55) U1(-4.8,-5.2) U2(-4,-5.2) U3(-3.2,-5.2) U4(-2.4,-5.2) U5(-1.6,-5.2) U6(-0.8,-5.2) U8(0.8,-5.2) U9(1.6,-5.2) U10(2.4,-5.2) U11(3.2,-5.2) U12(4,-5.2) U13(4.8,-5.2)
  silkscreen extent -5.7,-5.8 5.55,5.95, body extent -5.55,-5.8 5.55,5.8, height 1.05
ICC_P-WFBGA153_13X11P5_P050 [mm]
  round 0.23 smd mask+0.05: A1(-3.25,-3.25) A2(-3.25,-2.75) A3(-3.25,-2.25) A4(-3.25,-1.75) A5(-3.25,-1.25) A6(-3.25,-0.75) A7(-3.25,-0.25) A8(-3.25,0.25) A9(-3.25,0.75) A10(-3.25,1.25) A11(-3.25,1.75) A12(-3.25,2.25) A13(-3.25,2.75) A14(-3.25,3.25) B1(-2.75,-3.25) B2(-2.75,-2.75) B3(-2.75,-2.25) B4(-2.75,-1.75) B5(-2.75,-1.25) B6(-2.75,-0.75) B7(-2.75,-0.25) B8(-2.75,0.25) B9(-2.75,0.75) B10(-2.75,1.25) B11(-2.75,1.75) B12(-2.75,2.25) B13(-2.75,2.75) B14(-2.75,3.25) C1(-2.25,-3.25) C2(-2.25,-2.75) C3(-2.25,-2.25) C4(-2.25,-1.75) C5(-2.25,-1.25) C6(-2.25,-0.75) C7(-2.25,-0.25) C8(-2.25,0.25) C9(-2.25,0.75) C10(-2.25,1.25) C11(-2.25,1.75) C12(-2.25,2.25) C13(-2.25,2.75) C14(-2.25,3.25) D1(-1.75,-3.25) D2(-1.75,-2.75) D3(-1.75,-2.25) D4(-1.75,-1.75) D12(-1.75,2.25) D13(-1.75,2.75) D14(-1.75,3.25) E1(-1.25,-3.25) E2(-1.25,-2.75) E3(-1.25,-2.25) E5(-1.25,-1.25) E6(-1.25,-0.75) E7(-1.25,-0.25) E8(-1.25,0.25) E9(-1.25,0.75) E10(-1.25,1.25) E12(-1.25,2.25) E13(-1.25,2.75) E14(-1.25,3.25) F1(-0.75,-3.25) F2(-0.75,-2.75) F3(-0.75,-2.25) F5(-0.75,-1.25) F10(-0.75,1.25) F12(-0.75,2.25) F13(-0.75,2.75) F14(-0.75,3.25) G1(-0.25,-3.25) G2(-0.25,-2.75) G3(-0.25,-2.25) G5(-0.25,-1.25) G10(-0.25,1.25) G12(-0.25,2.25) G13(-0.25,2.75) G14(-0.25,3.25) H1(0.25,-3.25) H2(0.25,-2.75) H3(0.25,-2.25) H5(0.25,-1.25) H10(0.25,1.25) H12(0.25,2.25) H13(0.25,2.75) H14(0.25,3.25) J1(0.75,-3.25) J2(0.75,-2.75) J3(0.75,-2.25) J5(0.75,-1.25) J10(0.75,1.25) J12(0.75,2.25) J13(0.75,2.75) J14(0.75,3.25) K1(1.25,-3.25) K2(1.25,-2.75) K3(1.25,-2.25) K5(1.25,-1.25) K6(1.25,-0.75) K7(1.25,-0.25) K8(1.25,0.25) K9(1.25,0.75) K10(1.25,1.25) K12(1.25,2.25) K13(1.25,2.75) K14(1.25,3.25) L1(1.75,-3.25) L2(1.75,-2.75) L3(1.75,-2.25) L12(1.75,2.25) L13(1.75,2.75) L14(1.75,3.25) M1(2.25,-3.25) M2(2.25,-2.75) M3(2.25,-2.25) M4(2.25,-1.75) M5(2.25,-1.25) M6(2.25,-0.75) M7(2.25,-0.25) M8(2.25,0.25) M9(2.25,0.75) M10(2.25,1.25) M11(2.25,1.75) M12(2.25,2.25) M13(2.25,2.75) M14(2.25,3.25) N1(2.75,-3.25) N2(2.75,-2.75) N3(2.75,-2.25) N4(2.75,-1.75) N5(2.75,-1.25) N6(2.75,-0.75) N7(2.75,-0.25) N8(2.75,0.25) N9(2.75,0.75) N10(2.75,1.25) N11(2.75,1.75) N12(2.75,2.25) N13(2.75,2.75) N14(2.75,3.25) P1(3.25,-3.25) P2(3.25,-2.75) P3(3.25,-2.25) P4(3.25,-1.75) P5(3.25,-1.25) P6(3.25,-0.75) P7(3.25,-0.25) P8(3.25,0.25) P9(3.25,0.75) P10(3.25,1.25) P11(3.25,1.75) P12(3.25,2.25) P13(3.25,2.75) P14(3.25,3.25)
  silkscreen extent -6.78,-6.02 6.63,5.87, body extent -6.55,-5.8 6.55,5.8, height 1
ICC_TFBGA361_12X12_STM32MP157CAC3_P050-065 [mm] "IPC"
  round 0.23 smd mask+0.05: 1A2(-1.95,2.6) 1A3(-1.3,2.6) 1A4(-0.65,2.6) 1A5(0,2.6) 1A6(0.65,2.6) 1A7(1.3,2.6) 1A8(1.95,2.6) 1B1(-2.6,1.95) 1B2(-1.95,1.95) 1B3(-1.3,1.95) 1B4(-0.65,1.95) 1B5(0,1.95) 1B6(0.65,1.95) 1B7(1.3,1.95) 1B8(1.95,1.95) 1B9(2.6,1.95) 1C1(-2.6,1.3) 1C2(-1.95,1.3) 1C3(-1.3,1.3) 1C4(-0.65,1.3) 1C5(0,1.3) 1C6(0.65,1.3) 1C7(1.3,1.3) 1C8(1.95,1.3) 1C9(2.6,1.3) 1D1(-2.6,0.65) 1D2(-1.95,0.65) 1D3(-1.3,0.65) 1D4(-0.65,0.65) 1D5(0,0.65) 1D6(0.65,0.65) 1D7(1.3,0.65) 1D8(1.95,0.65) 1D9(2.6,0.65) 1E1(-2.6,0) 1E2(-1.95,0) 1E3(-1.3,0) 1E4(-0.65,0) 1E5(0,0) 1E6(0.65,0) 1E7(1.3,0) 1E8(1.95,0) 1E9(2.6,0) 1F1(-2.6,-0.65) 1F2(-1.95,-0.65) 1F3(-1.3,-0.65) 1F4(-0.65,-0.65) 1F5(0,-0.65) 1F6(0.65,-0.65) 1F7(1.3,-0.65) 1F8(1.95,-0.65) 1F9(2.6,-0.65) 1G1(-2.6,-1.3) 1G2(-1.95,-1.3) 1G3(-1.3,-1.3) 1G4(-0.65,-1.3) 1G5(0,-1.3) 1G6(0.65,-1.3) 1G7(1.3,-1.3) 1G8(1.95,-1.3) 1G9(2.6,-1.3) 1H1(-2.6,-1.95) 1H2(-1.95,-1.95) 1H3(-1.3,-1.95) 1H4(-0.65,-1.95) 1H5(0,-1.95) 1H6(0.65,-1.95) 1H7(1.3,-1.95) 1H8(1.95,-1.95) 1H9(2.6,-1.95) 1J2(-1.95,-2.6) 1J3(-1.3,-2.6) 1J4(-0.65,-2.6) 1J5(0,-2.6) 1J6(0.65,-2.6) 1J7(1.3,-2.6) 1J8(1.95,-2.6) A1(-5.5,5.5) A2(-5,5.5) A3(-4.5,5.5) A4(-4,5.5) A5(-3.5,5.5) A7(-2.5,5.5) A8(-2,5.5) A10(-1,5.5) A11(-0.5,5.5) A13(0.5,5.5) A14(1,5.5) A16(2,5.5) A17(2.5,5.5) A19(3.5,5.5) A20(4,5.5) A21(4.5,5.5) A22(5,5.5) A23(5.5,5.5) AA1(-5.5,-4.5) AA2(-5,-4.5) AA3(-4.5,-4.5) AA4(-4,-4.5) AA5(-3.5,-4.5) AA6(-3,-4.5) AA7(-2.5,-4.5) AA8(-2,-4.5) AA9(-1.5,-4.5) AA10(-1,-4.5) AA11(-0.5,-4.5) AA12(0,-4.5) AA13(0.5,-4.5) AA14(1,-4.5) AA15(1.5,-4.5) AA16(2,-4.5) AA17(2.5,-4.5) AA18(3,-4.5) AA19(3.5,-4.5) AA20(4,-4.5) AA21(4.5,-4.5) AA22(5,-4.5) AA23(5.5,-4.5) AB1(-5.5,-5) AB2(-5,-5) AB3(-4.5,-5) AB4(-4,-5) AB5(-3.5,-5) AB6(-3,-5) AB7(-2.5,-5) AB8(-2,-5) AB9(-1.5,-5) AB10(-1,-5) AB11(-0.5,-5) AB12(0,-5) AB13(0.5,-5) AB14(1,-5) AB15(1.5,-5) AB16(2,-5) AB17(2.5,-5) AB18(3,-5) AB19(3.5,-5) AB20(4,-5) AB21(4.5,-5) AB22(5,-5) AB23(5.5,-5) AC1(-5.5,-5.5) AC2(-5,-5.5) AC3(-4.5,-5.5) AC4(-4,-5.5) AC5(-3.5,-5.5) AC7(-2.5,-5.5) AC8(-2,-5.5) AC10(-1,-5.5) AC11(-0.5,-5.5) AC13(0.5,-5.5) AC14(1,-5.5) AC16(2,-5.5) AC17(2.5,-5.5) AC19(3.5,-5.5) AC20(4,-5.5) AC21(4.5,-5.5) AC22(5,-5.5) AC23(5.5,-5.5) B1(-5.5,5) B2(-5,5) B3(-4.5,5) B4(-4,5) B5(-3.5,5) B6(-3,5) B7(-2.5,5) B8(-2,5) B9(-1.5,5) B10(-1,5) B11(-0.5,5) B12(0,5) B13(0.5,5) B14(1,5) B15(1.5,5) B16(2,5) B17(2.5,5) B18(3,5) B19(3.5,5) B20(4,5) B21(4.5,5) B22(5,5) B23(5.5,5) C1(-5.5,4.5) C2(-5,4.5) C3(-4.5,4.5) C4(-4,4.5) C5(-3.5,4.5) C6(-3,4.5) C7(-2.5,4.5) C8(-2,4.5) C9(-1.5,4.5) C10(-1,4.5) C11(-0.5,4.5) C12(0,4.5) C13(0.5,4.5) C14(1,4.5) C15(1.5,4.5) C16(2,4.5) C17(2.5,4.5) C18(3,4.5) C19(3.5,4.5) C20(4,4.5) C21(4.5,4.5) C22(5,4.5) C23(5.5,4.5) D1(-5.5,4) D2(-5,4) D3(-4.5,4) D4(-4,4) D5(-3.5,4) D6(-3,4) D7(-2.5,4) D8(-2,4) D9(-1.5,4) D10(-1,4) D11(-0.5,4) D12(0,4) D13(0.5,4) D14(1,4) D15(1.5,4) D16(2,4) D17(2.5,4) D18(3,4) D19(3.5,4) D20(4,4) D21(4.5,4) D22(5,4) D23(5.5,4) E1(-5.5,3.5) E2(-5,3.5) E3(-4.5,3.5) E4(-4,3.5) E20(4,3.5) E21(4.5,3.5) E22(5,3.5) E23(5.5,3.5) F2(-5,3) F3(-4.5,3) F4(-4,3) F20(4,3) F21(4.5,3) F22(5,3) G1(-5.5,2.5) G2(-5,2.5) G3(-4.5,2.5) G4(-4,2.5) G20(4,2.5) G21(4.5,2.5) G22(5,2.5) G23(5.5,2.5) H1(-5.5,2) H2(-5,2) H3(-4.5,2) H4(-4,2) H20(4,2) H21(4.5,2) H22(5,2) H23(5.5,2) J2(-5,1.5) J3(-4.5,1.5) J4(-4,1.5) J20(4,1.5) J21(4.5,1.5) J22(5,1.5) K1(-5.5,1) K2(-5,1) K3(-4.5,1) K4(-4,1) K20(4,1) K21(4.5,1) K22(5,1) K23(5.5,1) L1(-5.5,0.5) L2(-5,0.5) L3(-4.5,0.5) L4(-4,0.5) L20(4,0.5) L21(4.5,0.5) L22(5,0.5) L23(5.5,0.5) M2(-5,0) M3(-4.5,0) M4(-4,0) M20(4,0) M21(4.5,0) M22(5,0) N1(-5.5,-0.5) N2(-5,-0.5) N3(-4.5,-0.5) N4(-4,-0.5) N20(4,-0.5) N21(4.5,-0.5) N22(5,-0.5) N23(5.5,-0.5) P1(-5.5,-1) P2(-5,-1) P3(-4.5,-1) P4(-4,-1) P20(4,-1) P21(4.5,-1) P22(5,-1) P23(5.5,-1) R2(-5,-1.5) R3(-4.5,-1.5) R4(-4,-1.5) R20(4,-1.5) R21(4.5,-1.5) R22(5,-1.5) T1(-5.5,-2) T2(-5,-2) T3(-4.5,-2) T4(-4,-2) T20(4,-2) T21(4.5,-2) T22(5,-2) T23(5.5,-2) U1(-5.5,-2.5) U2(-5,-2.5) U3(-4.5,-2.5) U4(-4,-2.5) U20(4,-2.5) U21(4.5,-2.5) U22(5,-2.5) U23(5.5,-2.5) V2(-5,-3) V3(-4.5,-3) V4(-4,-3) V20(4,-3) V21(4.5,-3) V22(5,-3) W1(-5.5,-3.5) W2(-5,-3.5) W3(-4.5,-3.5) W4(-4,-3.5) W20(4,-3.5) W21(4.5,-3.5) W22(5,-3.5) W23(5.5,-3.5) Y1(-5.5,-4) Y2(-5,-4) Y3(-4.5,-4) Y4(-4,-4) Y5(-3.5,-4) Y6(-3,-4) Y7(-2.5,-4) Y8(-2,-4) Y9(-1.5,-4) Y10(-1,-4) Y11(-0.5,-4) Y12(0,-4) Y13(0.5,-4) Y14(1,-4) Y15(1.5,-4) Y16(2,-4) Y17(2.5,-4) Y18(3,-4) Y19(3.5,-4) Y20(4,-4) Y21(4.5,-4) Y22(5,-4) Y23(5.5,-4)
  silkscreen extent -6.25,-6.07 6.07,6.25, body extent -6.07,-6.07 6.07,6.07, height 1.21
ICC_WFQFN44-EPAD_5X6_P040 [mm]
  rect 0.8x0.2 smd mask+0.05: 1(-2.45,2.2) 2(-2.45,1.8) 3(-2.45,1.4) 4(-2.45,1) 5(-2.45,0.6) 6(-2.45,0.2) 7(-2.45,-0.2) 8(-2.45,-0.6) 9(-2.45,-1) 10(-2.45,-1.4) 11(-2.45,-1.8) 12(-2.45,-2.2) 23(2.45,-2.2) 24(2.45,-1.8) 25(2.45,-1.4) 26(2.45,-1) 27(2.45,-0.6) 28(2.45,-0.2) 29(2.45,0.2) 30(2.45,0.6) 31(2.45,1) 32(2.45,1.4) 33(2.45,1.8) 34(2.45,2.2)
  rect 0.2x0.8 smd mask+0.05: 13(-1.8,-2.95) 14(-1.4,-2.95) 15(-1,-2.95) 16(-0.6,-2.95) 17(-0.2,-2.95) 18(0.2,-2.95) 19(0.6,-2.95) 20(1,-2.95) 21(1.4,-2.95) 22(1.8,-2.95) 35(1.8,2.95) 36(1.4,2.95) 37(1,2.95) 38(0.6,2.95) 39(0.2,2.95) 40(-0.2,2.95) 41(-0.6,2.95) 42(-1,2.95) 43(-1.4,2.95) 44(-1.8,2.95)
  rect 3.6x4.6 smd paste-1.8 mask+0.05: ep(0,0)
  silkscreen extent -2.5,-3 2.5,3, body extent -2.5,-3 2.5,3, height 0.81
IND_2520_TOKO_DFE252012P [mm]
  rect 0.8x2 smd mask+0.05: 1(-1,0) 2(1,0)
  silkscreen extent -1.35,-1.12 1.35,1.12, body extent -1.35,-1.1 1.35,1.1, height 2
R0402 [mm]
  rect 0.51x0.7 smd mask+0.05: 1(-0.45,0) 2(0.45,0)
  silkscreen extent 0,-0.3 0,0.3, body extent -0.52,-0.3 0.52,0.3, height 0.4
SWI_JIUBABA_C-TS-02H-2-5-B-V-T_R_BLUE [mm] "BLUE"
  rect 0.75x1 smd mask+0.05: 1(-2.225,0.75) 2(2.225,0.75) 3(-2.225,-0.75) 4(2.225,-0.75)
  silkscreen extent -1.85,-1.6 1.85,1.6, body extent -2.45,-1.6 2.45,1.6, height 2.6

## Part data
B1: library part MCD-00172, "Switch HW SMD blue"
C1 C2 C3 C4 C5 C6 C7 C8 C9 C10 C11 C12 C13 C17 C19 C20 C21 C61 C66 C71 C78 C80 C82 C149 C150: library part MCD-00006, "Capacitor, MLCC, 100nF, 16V, X7R, 10%, 0402, T=0.5mm"
C14 C15 C16: library part MCD-01124, "Capacitor, MLCC, 10uF, 10V, X5R, 10%, 0603, T=0.8mm"
C18 C31 C33 C39 C42 C46: library part MCD-00099, "Capacitor, MLCC, 10uF, 10V, X5R, 10%, 0603, T=0,8mm"
C29 C34 C38 C40: library part MCD-00100, "Capacitor, MLCC, 22uF, 6V3, X5R, 20%, 0603, T=0,8mm"
C30 C32 C35 C36 C37 C41 C45 C47 C48 C50 C53 C54 C55 C59 C70 C75 C76 C77 C84 C92 C94 C95 C96: library part MCD-00095, "Capacitor, MLCC, 1uF, 25V, X5R, 10%, 0402, T=0,5mm"
C43 C49 C51 C52: library part MCD-01356, "Capacitor, MLCC, 4.7uF, 6V3, X5R, 20%, 0402, T=0,5mm"
C44 C58: library part MCD-00011, "Capacitor, MLCC, 10nF, 16V, X7R, 10%, 0402, T=0.5mm"
C56 C57: library part MCD-01508, "Capacitor, MLCC, 820pF, 50V, X7R, 10%, 0402, T=0.55mm"
C67 C68 C69: library part MCD-01823, "Capacitor,MLCC,2.2uF,6V3,X5R,10%,0402,T=0.5"
C79 C81 C83: library part MCD-00012, "Capacitor, MLCC, 2.2uF, 10V, X5R, 10%, 0603, T=0,8mm"
L1 L2 L3 L4: library part MCD-01122, "Power Inductor ,1uH,4.3A max,+/-20%,0.042ohm,2520"
R24 R65: library part MCD-00120, "Resistor,240R,0402,1%,1/16W"
R37 R38: library part MCD-00068, "Resistor,1K5,0402,1%,1/16W"
R40 R49: library part MCD-00053, "Resistor,10K,0402,1%,1/16W"
R41: library part MCD-00052, "Resistor,0R,0402,5%,1/16W"
R43: library part MCD-00063, "Resistor,47K,0402,1%,1/16W"
R53: library part MCD-00067, "Resistor,100R,0402,1%,1/16W"
U1: library part MCD-00677, "MPU TFBGA12x12 secure boot+crypto"
U2: library part MCD-00209, "Memory,LPDDR3,8Gb,256Mbx32,1866MT/s,1V8,FBGA178"
U4: library part MCD-01650, "ST PMIC:  4 step-down + 1 advanced boost SMPS, 6 LDOs, 2 pwr switches, DDR Vref, NVM option 'A' for IO@3.3V"
U5: library part MCD-00110, "Memory,e-MMC,4GB,3V3,WFBGA,153pins"

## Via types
v1: diameter 0.4, hole 0.2, Top Layer to Bottom Layer, tented both sides, 258 vias
v2: diameter 0.25, hole 0.1, Top Layer to Signal Layer 1, tented top, 105 vias
v3: diameter 0.6, hole 0.3, Top Layer to Bottom Layer, tented both sides, 95 vias
v4: diameter 0.25, hole 0.1, Top Layer to Signal Layer 1, tented both sides, 6 vias

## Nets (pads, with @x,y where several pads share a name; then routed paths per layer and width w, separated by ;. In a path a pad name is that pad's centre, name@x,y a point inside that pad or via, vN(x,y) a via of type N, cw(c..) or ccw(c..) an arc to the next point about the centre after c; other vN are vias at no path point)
3V3: C32.2 C40.2 C78.2 C79.2 L4.2 U4.22 U4.27 U5.E6 U5.F5 U5.J10 U5.K9 | length 50.8
  Top Layer w0.1: v2(12.25,81.45) U4.27@12.25,82.025
  Top Layer w0.175: U5.J10@27.7,88.475 U5.K9@28.2,88.975 v1(28.2,89.45) ; U5.E6@29.7,86.475 U5.F5@30.2,86.975 v1(30.625,86.975)
  Top Layer w0.2: 9.725,82.5 U4.22@9.9,82.675 9.9,82.491
  Top Layer w0.3: 9.625,82.5 9.725,82.5
  Top Layer w0.4: C32.2@7.7,80.075 7.9,80.075 8.187,80.362 8.635,80.81 8.635,81.41 9.725,82.5
  Signal Layer 1 w0.2: v3(11.575,74.9) 12.25,75.575 v2(12.25,81.45)
  Signal Layer 4 w0.3: v3(8.3,80.25) 7.225,79.175 7.225,76.825 9.15,74.9 v3(10.2,74.9) v3(10.9,74.9) v3(11.575,74.9)
  Bottom Layer w0.13: C78.2@30.025,86.9 C78.2@30.125,87 ; v1@30.6,87 v1(30.625,86.975)
  Bottom Layer w0.3: v3(11.575,74.9) 17.275,80.6 17.275,82.625 18.775,84.125 22.575,84.125 25.25,86.8 25.25,87.475 C79.2@27.35,89.575 ; C79.2@27.475,89.45 28.175,89.45 28.188,89.437 29.325,88.3 29.325,87.6 C78.2@30.025,86.9 ; C78.2@30.125,87 v1@30.6,87
5V_VIN: C18.2 C31.2 C33.2 C39.2 C41.2 C51.2 R43.2 U4.8 U4.12 U4.19 U4.24 U4.28 U4.36 U4.37 | length 20.5
  Top Layer w0.2: 8.775,83.875 U4.19@9.9,83.875 ; 11.05,81.3 U4.24@11.05,82.025 ; U4.8@12.25,86.925 12.25,88.76 ; U4.28@12.65,82.025 12.65,80.975 13.625,80 C31.2@13.625,79.25 ; U4.36@15.8,83.075 16.45,83.075 C51.2@16.7,82.825 ; U4.37@15.8,83.475 16.825,83.475
  Top Layer w0.3: C41.2@7.7,83.325 8.25,83.875 8.775,83.875 ; v1(8.075,78.775) v1(8.55,78.775) v1(9,78.775) ; v3(18.575,81.45) 19.325,81.45 R43.2@19.461,81.586
  Top Layer w0.4: v3(4.725,83.15) v3(5.35,83.15) 5.735,82.765 7.335,82.765 7.7,83.13 C41.2@7.7,83.325
  Top Layer w0.45: 16.625,83.55 18.078,83.55 18.503,83.125 v3(18.575,83.125) ; C51.2@16.7,82.825 16.7,82.127 17.377,81.45 v3(18.575,81.45)
  other v1: 13.225,78.725 13.725,78.725 14.2,78.725
  other v3: 6.075,88.575 6.075,89.2 6.075,89.825 11.85,89.9 12.55,89.9
DDR_A0: U1.L20 U2.R2 | length 28.2
  Top Layer w0.12: v1(35.4,63.675) 35.625,63.45 35.75,63.45 U1.L20@36,63.2 ; v1(57.7,66.525) 57.775,66.525 U2.R2@58.1,66.2
  Bottom Layer w0.12: v1(35.4,63.675) 35.4,64.309 34.975,64.734 34.975,66.269 36.581,67.875 50.075,67.875 50.225,67.725 50.62,67.725 50.88,67.465 53.815,67.465 53.96,67.61 56.615,67.61 v1(57.7,66.525)
DDR_A1: U1.P22 U2.P2 | length 28.6
  Top Layer w0.09: v1(35.6,63.075) 35.725,63.075 35.85,62.95 36.1,62.95 36.255,62.795 36.255,62.04 36.345,61.95 36.6,61.95 36.85,61.7 U1.P22@37,61.7
  Top Layer w0.12: v1(56.9,65.875) 57.775,65.875 U2.P2@58.1,65.55
  Bottom Layer w0.12: v1(35.6,63.075) 35.775,63.25 35.775,64.291 35.29,64.776 35.29,65.574 35.506,65.79 42.85,65.79 42.9,65.74 43.455,65.74 43.575,65.86 44.615,65.86 46.944,65.86 47.249,65.555 52.636,65.555 52.751,65.44 53.049,65.44 53.484,65.875 v1(56.9,65.875)
DDR_A2: U1.J20 U2.N2 | length 27.3
  Top Layer w0.12: v1(35.575,66.275) 35.535,66.275 35.22,65.96 35.22,64.755 35.775,64.2 U1.J20@36,64.2 ; U2.N2@58.1,64.9 58.165,64.9 58.495,65.23 v1@58.5,65.235
  Bottom Layer w0.12: v1(35.575,66.275) 38.2,66.275 39.12,67.195 50.23,67.195 50.555,66.87 56.761,66.87 58.401,65.23 v1@58.475,65.23
  other v1: 58.5,65.225
DDR_A3: U1.K22 U2.N3 | length 27.7
  Top Layer w0.1: U1.K22@37,63.696 37.25,63.446 37.754,63.446 v1(37.925,63.275)
  Top Layer w0.12: v1(56.9,64.575) 56.975,64.575 U2.N3@57.3,64.9
  Bottom Layer w0.12: v1(37.925,63.275) 37.9,63.3 37.925,63.325 37.925,63.575 37.77,63.73 37.77,64 37.88,64.11 38.265,64.11 38.407,63.968 38.407,63.675 38.537,63.545 38.826,63.545 38.956,63.675 38.956,63.966 39.1,64.11 39.49,64.11 39.805,63.795 40.07,63.795 40.35,64.075 40.738,64.075 41.018,63.795 41.77,63.795 42.075,64.1 42.725,64.1 42.85,63.975 42.85,63.523 42.999,63.374 43.2,63.374 43.325,63.499 43.325,63.985 43.45,64.11 43.688,64.11 43.85,63.948 43.85,63.2 43.975,63.075 44.175,63.075 44.875,63.775 45.2,63.775 46.025,62.95 46.55,62.95 46.7,63.1 46.95,63.1 47.16,62.89 48.557,62.89 49.022,62.425 51.15,62.425 51.35,62.625 54.375,62.625 55.017,63.268 55.017,63.463 54.75,63.73 54.75,64.24 54.855,64.345 56.68,64.345 v1@56.9,64.565
DDR_A4: U1.V20 U2.M3 | length 26
  Top Layer w0.12: v1@35.641,60.95 35.29,60.599 35.29,60.301 35.62,59.97 35.73,59.97 U1.V20@36,59.7 ; v1(56.9,63.925) 56.975,63.925 U2.M3@57.3,64.25
  Bottom Layer w0.12: v1(35.65,60.95) 36.3,60.95 37.575,62.225 38.1,62.225 39.25,63.375 42.404,63.375 43.124,62.655 45.17,62.655 45.365,62.46 48.369,62.46 48.824,62.005 51.33,62.005 51.685,62.36 52.891,62.36 53.026,62.225 54.569,62.225 56.269,63.925 v1(56.9,63.925)
DDR_A5: U1.H20 U2.F3 | length 26.4
  Top Layer w0.12: v1(35.65,64.925) 35.775,64.925 U1.H20@36,64.7 ; v1(52.9,63.275) 53.428,63.275 54.44,62.263 54.44,62.015 54.1,61.675 54.1,60.82 54.25,60.67 56.73,60.67 57.05,60.35 U2.F3@57.3,60.35
  Bottom Layer w0.12: v1@35.65,64.95 44.036,64.95 44.311,64.675 46.137,64.675 46.562,64.25 47.156,64.25 47.531,64.625 48.725,64.625 49.25,64.1 49.491,64.1 49.916,64.525 50.5,64.525 50.7,64.325 50.7,63.925 51.125,63.5 51.675,63.5 51.875,63.7 52.475,63.7 v1(52.9,63.275)
DDR_A6: U1.W20 U2.E3 | length 25.8
  Top Layer w0.12: v1(35.275,59.6) 35.631,59.6 U1.W20@36,59.231 ; v1(56.9,59.375) 57.225,59.7 U2.E3@57.3,59.7
  Bottom Layer w0.12: v1@35.289,59.586 38.064,59.586 38.275,59.375 38.275,57.725 38.75,57.25 49.75,57.25 50.275,57.775 54.95,57.775 55.375,58.2 55.725,58.2 v1(56.9,59.375)
DDR_A7: U1.E20 U2.E2 | length 26.1
  Top Layer w0.12: v1(35.65,65.425) 35.65,65.841 U1.E20@36,66.191 ; v1@53.786,63.611 54.767,62.63 55.023,62.63 55.325,62.328 55.325,62.222 55.577,61.97 55.833,61.97 56.099,61.703 56.099,61.598 56.372,61.325 56.628,61.325 56.9,61.053 56.9,60.948 57.177,60.67 57.433,60.67 57.62,60.483 57.62,60.304 57.8,60.124 57.8,60 U2.E2@58.1,59.7
  Bottom Layer w0.12: v1(35.65,65.425) 35.705,65.37 44.23,65.37 44.465,65.135 52.262,65.135 v1@53.786,63.611
  other v1: 53.775,63.6
DDR_A8: U1.Y20 U2.D2 | length 25
  Top Layer w0.12: v1@35.585,59.126 U1.Y20@36,58.711 ; v1(57.7,58.725) 58.025,59.05 U2.D2@58.1,59.05
  Bottom Layer w0.12: v1(35.575,59.125) 37.875,56.825 50.05,56.825 50.41,57.185 55.535,57.185 57.075,58.725 v1(57.7,58.725)
DDR_A9: U1.G20 U2.C2 | length 27.8
  Top Layer w0.09: U1.G20@36,65.2 36.245,64.955 36.245,63.085 36.38,62.95 36.67,62.95 36.75,62.87 36.75,62.111 36.916,61.945 37.655,61.945 v1(38.025,61.575)
  Top Layer w0.12: U2.C2@58.1,58.4 58.175,58.4 v1(58.5,58.725)
  Bottom Layer w0.12: v1(38.025,61.575) 40.71,61.575 40.925,61.79 41.91,61.79 43.875,59.825 48.5,59.825 49,59.325 51.06,59.325 51.475,59.74 57.485,59.74 v1(58.5,58.725)
DDR_CKE: R49.2 U1.T20 U2.K3 | length 30.6
  Top Layer w0.12: v1(35.65,60.45) 35.75,60.45 U1.T20@36,60.7 ; v1(56.9,62.625) 57.225,62.95 U2.K3@57.3,62.95 57.62,63.27 60.72,63.27 61.025,63.575 61.025,63.92 R49.2@61.025,63.925
  Bottom Layer w0.12: v1(35.65,60.45) 36.391,60.45 37.876,61.935 38.276,61.935 39.291,62.95 42.235,62.95 42.95,62.235 44.765,62.235 45.685,61.315 49.065,61.315 49.16,61.41 50.48,61.41 51.1,60.79 56.705,60.79 57.3,61.385 57.3,62.225 v1(56.9,62.625)
DDR_CLK_N: R53.2 U1.N23 U2.J2 | length 31.4
  Top Layer w0.1: U1.N23@37.5,62.2 37.52,62.22 39.28,62.22 v1(39.425,62.075) ; U2.J2@58.1,62.3 58.025,62.3 v1(57.7,62.625) 58.53,62.625 58.725,62.43 59.995,62.43 60.325,62.76 R53.2@60.375,62.76
  Bottom Layer w0.1: v1(39.425,62.075) 39.55,62.2 42.08,62.2 42.78,61.5 44.205,61.5 45.455,60.25 50.05,60.25 50.15,60.15 57.825,60.15 58.38,59.595 58.92,59.595 59.225,59.9 59.225,61.225 59.8,61.8 59.8,62.2 59.45,62.55 58.9,62.55 58.755,62.405 57.92,62.405 v1(57.7,62.625)
DDR_CLK_P: R53.1 U1.N22 U2.J3 | length 31.3
  Top Layer w0.1: U1.N22@37,62.2 37.25,62.45 39.3,62.45 v1(39.425,62.575) ; U2.J3@57.3,62.3 57.375,62.3 v1(57.7,61.975) 58.5,61.975 58.725,62.2 59.995,62.2 60.335,61.86 R53.1@60.375,61.86
  Bottom Layer w0.1: v1(39.425,62.575) 39.55,62.45 42.155,62.45 42.875,61.73 44.3,61.73 45.55,60.48 50.145,60.48 50.245,60.38 57.92,60.38 58.475,59.825 58.825,59.825 58.995,59.995 58.995,61.32 59.57,61.895 59.57,62.105 59.355,62.32 58.995,62.32 58.85,62.175 57.9,62.175 v1(57.7,61.975)
DDR_CSN: U1.M22 U2.L3 | length 27.5
  Top Layer w0.12: U1.M22@37,62.7 37.125,62.825 v1(37.7,62.825) ; U2.L3@57.3,63.6 57.35,63.6 v1(57.675,63.925)
  Bottom Layer w0.12: v1(37.7,62.825) 37.35,63.175 37.35,64.225 37.655,64.53 40.97,64.53 41.225,64.275 41.575,64.275 41.83,64.53 43.862,64.53 44.137,64.255 45.576,64.255 46.131,63.7 47.2,63.7 47.7,64.2 48.259,64.2 49.099,63.36 49.84,63.36 50.12,63.08 52.42,63.08 52.585,62.915 53.59,62.915 53.775,63.1 53.95,63.1 54.225,63.375 54.225,64.65 54.35,64.775 56.35,64.775 56.9,65.325 57.4,65.325 57.675,65.05 v1(57.675,63.925)
DDR_DQ0: U1.E22 U2.P9 | length 19.4
  Top Layer w0.09: U1.E22@37,66.196 37.153,66.196 37.398,65.951 37.926,65.951 38.05,66.075 39.197,66.075
  Top Layer w0.12: 39.197,66.078 39.821,66.701 41.157,66.701 41.701,67.245 42.455,67.245 42.585,67.375 42.585,67.948 43.467,68.83 44.024,68.83 44.124,68.73 44.311,68.73 44.411,68.83 46.473,68.83 47.44,67.863 47.44,67.228 ; 47.44,67.225 47.44,67.228 ; U2.P9@52.498,65.552 52.248,65.552 51.927,65.23 50.745,65.23 50.42,65.555 50.42,65.76 50.3,65.88 49.977,65.88 49.857,65.76 49.296,65.76 48.666,66.39 48.278,66.39 47.44,67.228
